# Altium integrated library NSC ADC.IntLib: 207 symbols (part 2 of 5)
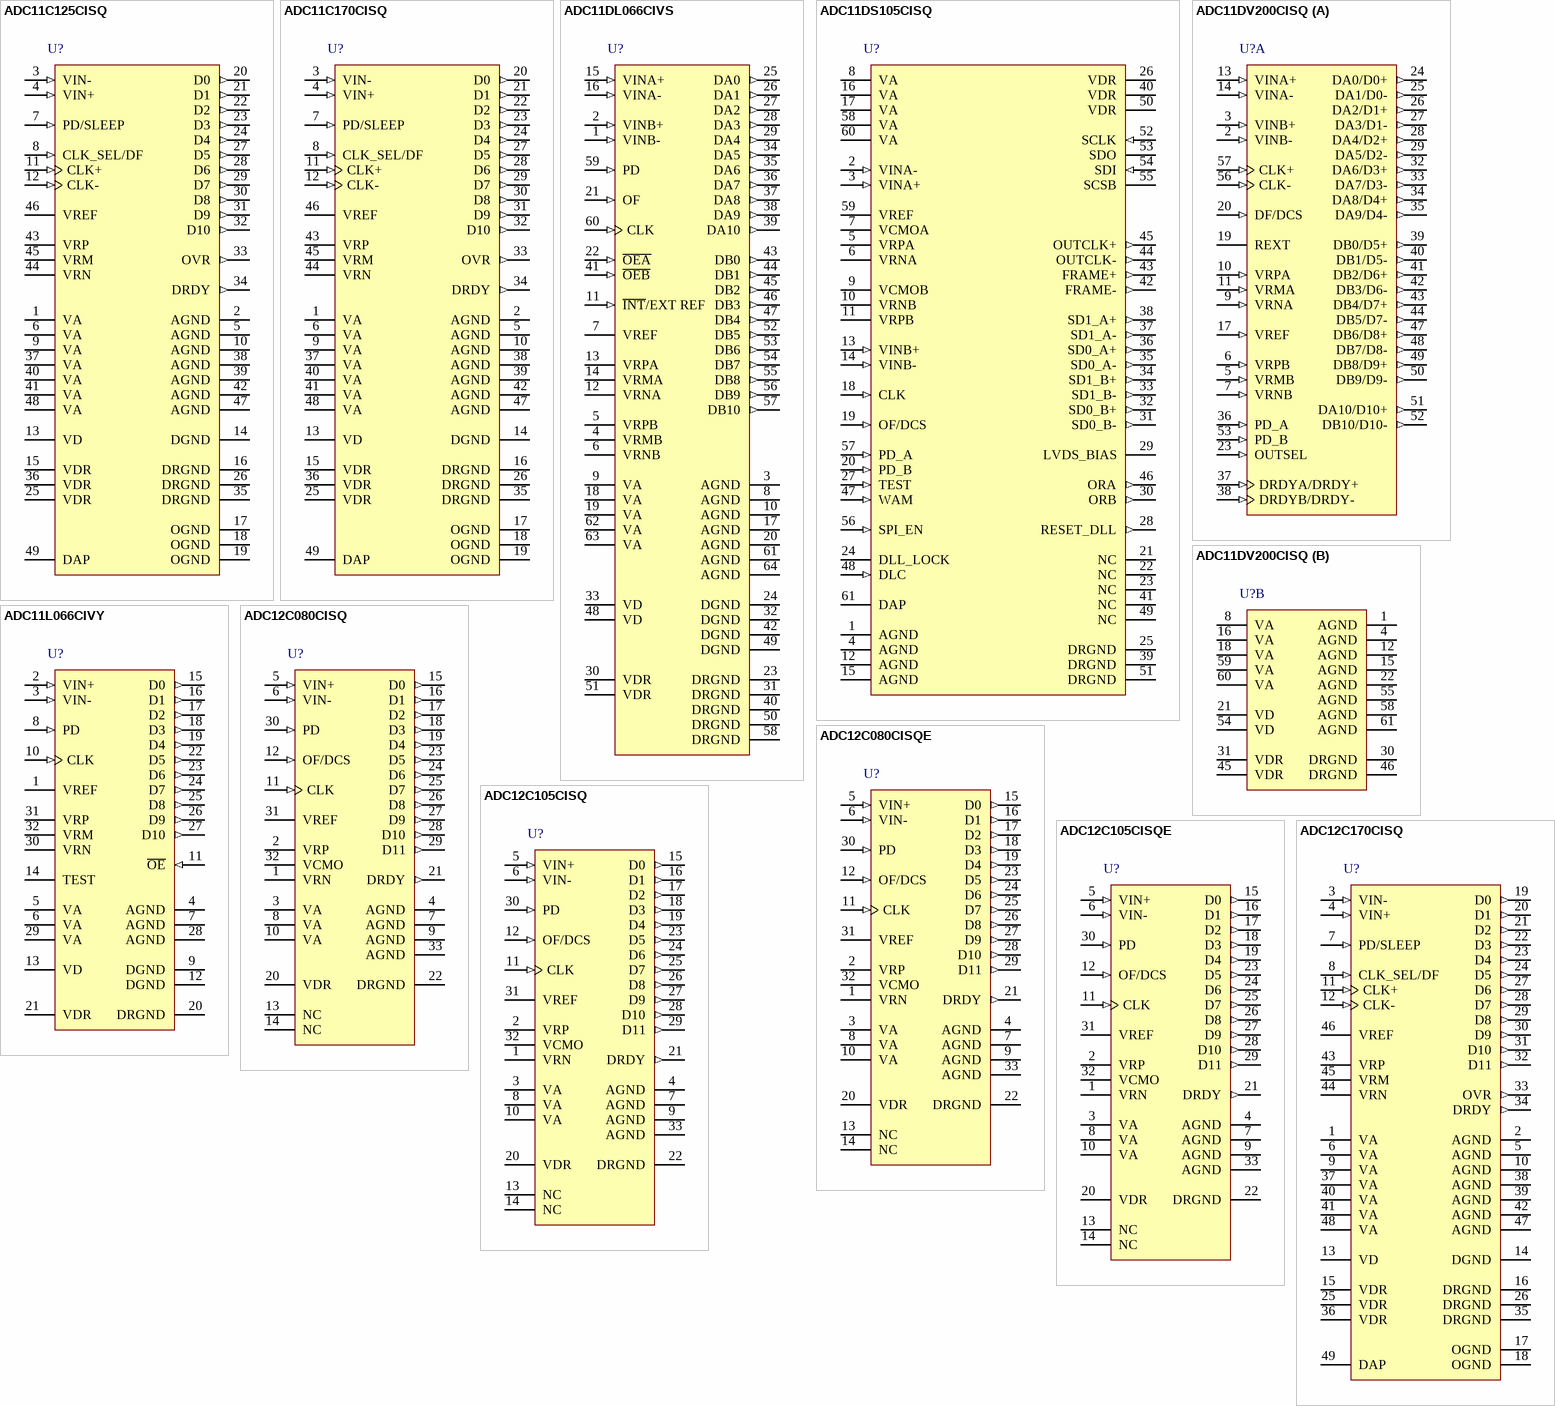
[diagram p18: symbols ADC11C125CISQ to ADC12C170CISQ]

## ADC11DS105CISQ
designator U?
Dual 11-Bit, 105 MSPS A/D Converter with Serial LVDS Outputs; PartNumber: ADC11DS105CISQ; Manufacturer: National Semiconductor; CompType: ADC IC; PackageTopMarking: NS*UZXYTT*11DS105; PowerWise: N
footprint SQA60A (QFN, 60-Leads, Body 9x9mm, Pitch 0.5mm, NSC Recommended)
pins: 1 AGND (power), 2 VINA- (in), 3 VINA+ (in), 4 AGND (power), 5 VRPA, 6 VRNA, 7 VCMOA, 8 VA (power), 9 VCMOB, 10 VRNB, 11 VRPB, 12 AGND (power), 13 VINB+ (in), 14 VINB- (in), 15 AGND (power), 16 VA (power), 17 VA (power), 18 CLK (in), 19 OF/DCS (in), 20 PD_B (in), 21 NC, 22 NC, 23 NC, 24 DLL_LOCK, 25 DRGND (power), 26 VDR, 27 TEST (in), 28 RESET_DLL (out), 29 LVDS_BIAS, 30 ORB (out), 31 SD0_B- (out), 32 SD0_B+ (out), 33 SD1_B- (out), 34 SD1_B+ (out), 35 SD0_A- (out), 36 SD0_A+ (out), 37 SD1_A- (out), 38 SD1_A+ (out), 39 DRGND (power), 40 VDR, 41 NC, 42 FRAME- (out), 43 FRAME+ (out), 44 OUTCLK- (out), 45 OUTCLK+ (out), 46 ORA (out), 47 WAM (in), 48 DLC (in), 49 NC, 50 VDR, 51 DRGND (power), 52 SCLK (in), 53 SDO (hiz), 54 SDI (in), 55 SCSB, 56 SPI_EN (in), 57 PD_A (in), 58 VA (power), 59 VREF, 60 VA (power), 61 DAP

## ADC11DV200CISQ
designator U?
Dual 11-bit, 200 MSPS Low-Power A/D Converter with Parallel LVDS/CMOS Outputs; PartNumber: ADC11DV200CISQ; Manufacturer: National Semiconductor; CompType: ADC IC; PackageTopMarking: NS*UZXYTT*11DV200*CISQ; PowerWise: N
footprint SQA60A (QFN, 60-Leads, Body 9x9mm, Pitch 0.5mm, NSC Recommended)
part A pins: 2 VINB- (in), 3 VINB+ (in), 5 VRMB (in), 6 VRPB (in), 7 VRNB (in), 9 VRNA (in), 10 VRPA (in), 11 VRMA (in), 13 VINA+ (in), 14 VINA- (in), 17 VREF (in), 19 REXT, 20 DF/DCS (in), 23 OUTSEL (in), 24 DA0/D0+ (out), 25 DA1/D0- (out), 26 DA2/D1+ (out), 27 DA3/D1- (out), 28 DA4/D2+ (out), 29 DA5/D2- (out), 32 DA6/D3+ (out), 33 DA7/D3- (out), 34 DA8/D4+ (out), 35 DA9/D4- (out), 36 PD_A (in), 37 DRDYA/DRDY+ (in), 38 DRDYB/DRDY- (in), 39 DB0/D5+ (out), 40 DB1/D5- (out), 41 DB2/D6+ (out), 42 DB3/D6- (out), 43 DB4/D7+ (out), 44 DB5/D7- (out), 47 DB6/D8+ (out), 48 DB7/D8- (out), 49 DB8/D9+ (out), 50 DB9/D9- (out), 51 DA10/D10+ (out), 52 DB10/D10- (out), 53 PD_B (in), 56 CLK- (in), 57 CLK+ (in)
part B pins: 1 AGND (power), 4 AGND (power), 8 VA (power), 12 AGND (power), 15 AGND (power), 16 VA (power), 18 VA (power), 21 VD (power), 22 AGND (power), 30 DRGND (power), 31 VDR (power), 45 VDR (power), 46 DRGND (power), 54 VD (power), 55 AGND (power), 58 AGND (power), 59 VA (power), 60 VA (power), 61 AGND (power)

## ADC11L066CIVY
designator U?
11-Bit, 66 MSPS, 450 MHz Bandwidth A/D Converter with Internal Sample-and-Hold; PartNumber: ADC11L066CIVY; Manufacturer: National Semiconductor; CompType: ADC IC; PackageTopMarking: NSUZXYTT*ADC11L0*66CIVY; PowerWise: N
footprint VBE32A_N (Thin QFP, 32-Leads, Body 7x7mm, Pitch 0.8mm, IPC Medium Density)
footprint VBE32A_L (Thin QFP, 32-Leads, Body 7x7mm, Pitch 0.8mm, IPC High Density)
footprint VBE32A_M (Thin QFP, 32-Leads, Body 7x7mm, Pitch 0.8mm, IPC Low Density)
pins: 1 VREF (power), 2 VIN+ (in), 3 VIN- (in), 4 AGND (power), 5 VA (power), 6 VA (power), 7 AGND (power), 8 PD (in), 9 DGND (power), 10 CLK (in), 11 ~{OE} (in), 12 DGND (power), 13 VD (power), 14 TEST, 15 D0 (out), 16 D1 (out), 17 D2 (out), 18 D3 (out), 19 D4 (out), 20 DRGND (power), 21 VDR (power), 22 D5 (out), 23 D6 (out), 24 D7 (out), 25 D8 (out), 26 D9 (out), 27 D10 (out), 28 AGND (power), 29 VA (power), 30 VRN, 31 VRP, 32 VRM

## ADC12C080CISQ
designator U?
12-Bit, 65/80 MSPS A/D Converter; PartNumber: ADC12C080CISQ; Manufacturer: National Semiconductor; CompType: ADC IC; PackageTopMarking: NS*UZXYTT*12C080; PowerWise: Y
footprint SQA32A (QFN, 32-Leads, Body 5x5mm, Pitch 0.5mm, NSC Recommended)
pins: 1 VRN, 2 VRP, 3 VA (power), 4 AGND (power), 5 VIN+ (in), 6 VIN- (in), 7 AGND (power), 8 VA (power), 9 AGND (power), 10 VA (power), 11 CLK (in), 12 OF/DCS (in), 13 NC, 14 NC, 15 D0 (out), 16 D1 (out), 17 D2 (out), 18 D3 (out), 19 D4 (out), 20 VDR (power), 21 DRDY (out), 22 DRGND (power), 23 D5 (out), 24 D6 (out), 25 D7 (out), 26 D8 (out), 27 D9 (out), 28 D10 (out), 29 D11 (out), 30 PD (in), 31 VREF (power), 32 VCMO, 33 AGND (power)

## ADC12C080CISQE
designator U?
12-Bit, 65/80 MSPS A/D Converter; PartNumber: ADC12C080CISQE; Manufacturer: National Semiconductor; CompType: ADC IC; PackageTopMarking: NS*UZXYTT*12C080E
footprint SQA32A (QFN, 32-Leads, Body 5x5mm, Pitch 0.5mm, NSC Recommended)
pins: 1 VRN, 2 VRP, 3 VA (power), 4 AGND (power), 5 VIN+ (in), 6 VIN- (in), 7 AGND (power), 8 VA (power), 9 AGND (power), 10 VA (power), 11 CLK (in), 12 OF/DCS (in), 13 NC, 14 NC, 15 D0 (out), 16 D1 (out), 17 D2 (out), 18 D3 (out), 19 D4 (out), 20 VDR (power), 21 DRDY (out), 22 DRGND (power), 23 D5 (out), 24 D6 (out), 25 D7 (out), 26 D8 (out), 27 D9 (out), 28 D10 (out), 29 D11 (out), 30 PD (in), 31 VREF (power), 32 VCMO, 33 AGND (power)

## ADC12C105CISQ
designator U?
12-Bit, 105 MSPS A/D Converter; PartNumber: ADC12C105CISQ; Manufacturer: National Semiconductor; CompType: ADC IC; PackageTopMarking: NS*UZXYTT*12C105; PowerWise: Y
footprint SQA32A (QFN, 32-Leads, Body 5x5mm, Pitch 0.5mm, NSC Recommended)
pins: 1 VRN, 2 VRP, 3 VA (power), 4 AGND (power), 5 VIN+ (in), 6 VIN- (in), 7 AGND (power), 8 VA (power), 9 AGND (power), 10 VA (power), 11 CLK (in), 12 OF/DCS (in), 13 NC, 14 NC, 15 D0 (out), 16 D1 (out), 17 D2 (out), 18 D3 (out), 19 D4 (out), 20 VDR (power), 21 DRDY (out), 22 DRGND (power), 23 D5 (out), 24 D6 (out), 25 D7 (out), 26 D8 (out), 27 D9 (out), 28 D10 (out), 29 D11 (out), 30 PD (in), 31 VREF (power), 32 VCMO, 33 AGND (power)

## ADC12C105CISQE
designator U?
12-Bit, 105 MSPS A/D Converter; PartNumber: ADC12C105CISQE; Manufacturer: National Semiconductor; CompType: ADC IC; PackageTopMarking: NS*UZXYTT*12C105E
footprint SQA32A (QFN, 32-Leads, Body 5x5mm, Pitch 0.5mm, NSC Recommended)
pins: 1 VRN, 2 VRP, 3 VA (power), 4 AGND (power), 5 VIN+ (in), 6 VIN- (in), 7 AGND (power), 8 VA (power), 9 AGND (power), 10 VA (power), 11 CLK (in), 12 OF/DCS (in), 13 NC, 14 NC, 15 D0 (out), 16 D1 (out), 17 D2 (out), 18 D3 (out), 19 D4 (out), 20 VDR (power), 21 DRDY (out), 22 DRGND (power), 23 D5 (out), 24 D6 (out), 25 D7 (out), 26 D8 (out), 27 D9 (out), 28 D10 (out), 29 D11 (out), 30 PD (in), 31 VREF (power), 32 VCMO, 33 AGND (power)

## ADC12C170CISQ
designator U?
12-Bit, 170 MSPS, 1.1 GHz Bandwidth A/D Converter with CMOS Outputs; PartNumber: ADC12C170CISQ; Manufacturer: National Semiconductor; CompType: ADC IC; PackageTopMarking: NS*UZXYTT*ADC12C170; PowerWise: Y
footprint SQA48A (QFN, 48-Leads, Body 7x7mm, Pitch 0.5mm, NSC Recommended)
pins: 1 VA (power), 2 AGND (power), 3 VIN- (in), 4 VIN+ (in), 5 AGND (power), 6 VA (power), 7 PD/SLEEP (in), 8 CLK_SEL/DF (in), 9 VA (power), 10 AGND (power), 11 CLK+ (in), 12 CLK- (in), 13 VD (power), 14 DGND (power), 15 VDR (power), 16 DRGND (power), 17 OGND (power), 18 OGND (power), 19 D0 (out), 20 D1 (out), 21 D2 (out), 22 D3 (out), 23 D4 (out), 24 D5 (out), 25 VDR (power), 26 DRGND (power), 27 D6 (out), 28 D7 (out), 29 D8 (out), 30 D9 (out), 31 D10 (out), 32 D11 (out), 33 OVR (out), 34 DRDY (out), 35 DRGND (power), 36 VDR (power), 37 VA (power), 38 AGND (power), 39 AGND (power), 40 VA (power), 41 VA (power), 42 AGND (power), 43 VRP, 44 VRN, 45 VRM, 46 VREF (power), 47 AGND (power), 48 VA (power), 49 DAP (power)

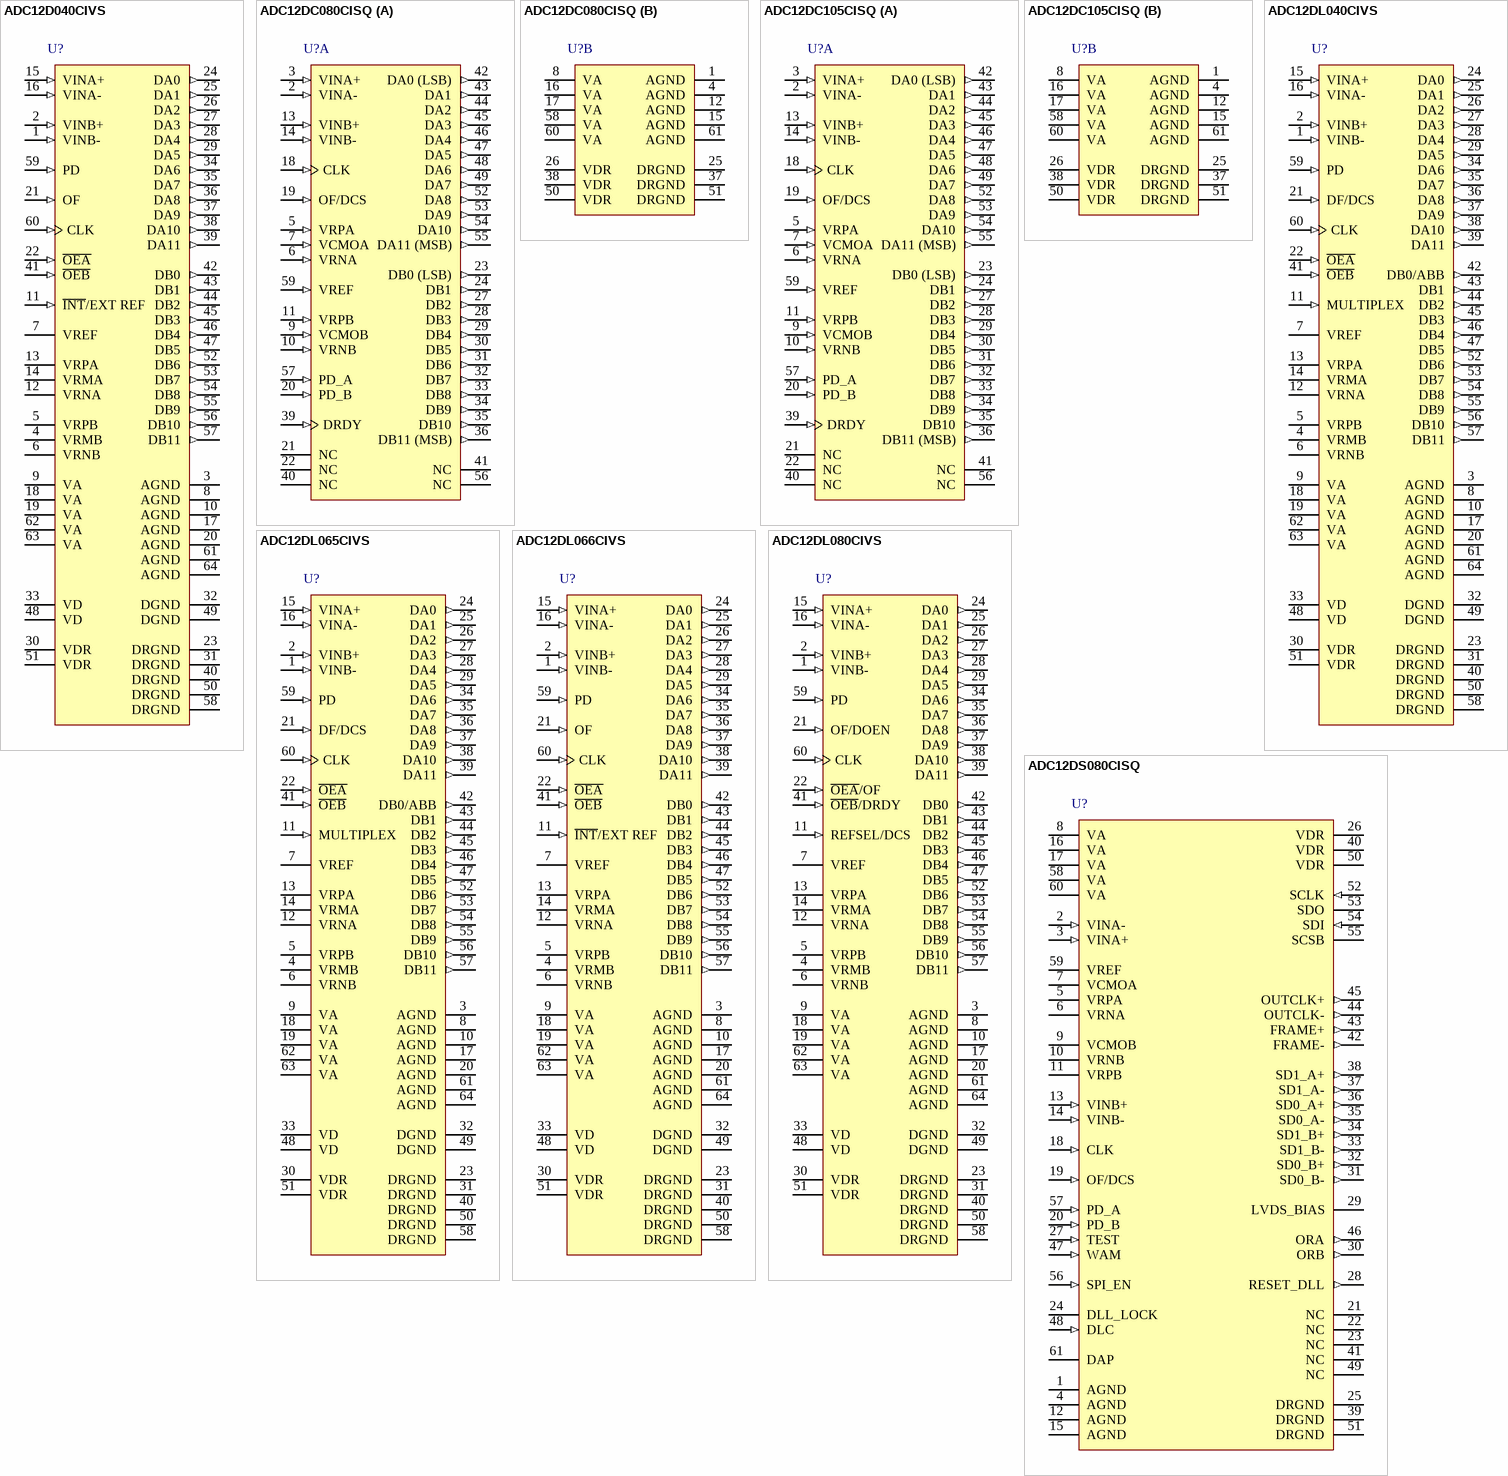
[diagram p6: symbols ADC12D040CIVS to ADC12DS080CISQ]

## ADC12D040CIVS
designator U?
Dual 12-Bit, 40 MSPS, 600 mW A/D Converter with Internal/External Reference; PartNumber: ADC12D040CIVS; Manufacturer: National Semiconductor; CompType: ADC IC; PackageTopMarking: NSUZXYYTT*ADC12D040*CIVS; PowerWise: N
footprint VEC64A_N (Thin QFP, 64-Leads, Body 10x10mm, Pitch 0.5mm, IPC Medium Density)
footprint VEC64A_L (Thin QFP, 64-Leads, Body 10x10mm, Pitch 0.5mm, IPC High Density)
footprint VEC64A_M (Thin QFP, 64-Leads, Body 10x10mm, Pitch 0.5mm, IPC Low Density)
pins: 1 VINB- (in), 2 VINB+ (in), 3 AGND (power), 4 VRMB, 5 VRPB, 6 VRNB, 7 VREF (power), 8 AGND (power), 9 VA (power), 10 AGND (power), 11 ~{INT}/EXT REF (in), 12 VRNA, 13 VRPA, 14 VRMA, 15 VINA+ (in), 16 VINA- (in), 17 AGND (power), 18 VA (power), 19 VA (power), 20 AGND (power), 21 OF (in), 22 ~{OEA} (in), 23 DRGND (power), 24 DA0 (out), 25 DA1 (out), 26 DA2 (out), 27 DA3 (out), 28 DA4 (out), 29 DA5 (out), 30 VDR (power), 31 DRGND (power), 32 DGND (power), 33 VD (power), 34 DA6 (out), 35 DA7 (out), 36 DA8 (out), 37 DA9 (out), 38 DA10 (out), 39 DA11 (out), 40 DRGND (power), 41 ~{OEB} (in), 42 DB0 (out), 43 DB1 (out), 44 DB2 (out), 45 DB3 (out), 46 DB4 (out), 47 DB5 (out), 48 VD (power), 49 DGND (power), 50 DRGND (power), 51 VDR (power), 52 DB6 (out), 53 DB7 (out), 54 DB8 (out), 55 DB9 (out), 56 DB10 (out), 57 DB11 (out), 58 DRGND (power), 59 PD (in), 60 CLK (in), 61 AGND (power), 62 VA (power), 63 VA (power), 64 AGND (power)

## ADC12DC080CISQ
designator U?
Dual 12-Bit, 80 MSPS A/D Converter with CMOS Outputs; PartNumber: ADC12DC080CISQ; Manufacturer: National Semiconductor; CompType: ADC IC; PackageTopMarking: NS*UZXYTT*12DC080*CISQ; PowerWise: Y
footprint SQA60A (QFN, 60-Leads, Body 9x9mm, Pitch 0.5mm, NSC Recommended)
part A pins: 2 VINA- (in), 3 VINA+ (in), 5 VRPA (in), 6 VRNA (in), 7 VCMOA (in), 9 VCMOB (in), 10 VRNB (in), 11 VRPB (in), 13 VINB+ (in), 14 VINB- (in), 18 CLK (in), 19 OF/DCS (in), 20 PD_B (in), 21 NC, 22 NC, 23 DB0 (LSB) (out), 24 DB1 (out), 27 DB2 (out), 28 DB3 (out), 29 DB4 (out), 30 DB5 (out), 31 DB6 (out), 32 DB7 (out), 33 DB8 (out), 34 DB9 (out), 35 DB10 (out), 36 DB11 (MSB) (out), 39 DRDY (in), 40 NC, 41 NC, 42 DA0 (LSB) (out), 43 DA1 (out), 44 DA2 (out), 45 DA3 (out), 46 DA4 (out), 47 DA5 (out), 48 DA6 (out), 49 DA7 (out), 52 DA8 (out), 53 DA9 (out), 54 DA10 (out), 55 DA11 (MSB) (out), 56 NC, 57 PD_A (in), 59 VREF (in)
part B pins: 1 AGND (power), 4 AGND (power), 8 VA (power), 12 AGND (power), 15 AGND (power), 16 VA (power), 17 VA (power), 25 DRGND (power), 26 VDR (power), 37 DRGND (power), 38 VDR (power), 50 VDR (power), 51 DRGND (power), 58 VA (power), 60 VA (power), 61 AGND (power)

## ADC12DC105CISQ
designator U?
Dual 12-Bit, 105 MSPS A/D Converter with CMOS Outputs; PartNumber: ADC12DC105CISQ; Manufacturer: National Semiconductor; CompType: ADC IC; PackageTopMarking: NS*UZXYTT*12DC105*CISQ; PowerWise: Y
footprint SQA60A (QFN, 60-Leads, Body 9x9mm, Pitch 0.5mm, NSC Recommended)
part A pins: 2 VINA- (in), 3 VINA+ (in), 5 VRPA (in), 6 VRNA (in), 7 VCMOA (in), 9 VCMOB (in), 10 VRNB (in), 11 VRPB (in), 13 VINB+ (in), 14 VINB- (in), 18 CLK (in), 19 OF/DCS (in), 20 PD_B (in), 21 NC, 22 NC, 23 DB0 (LSB) (out), 24 DB1 (out), 27 DB2 (out), 28 DB3 (out), 29 DB4 (out), 30 DB5 (out), 31 DB6 (out), 32 DB7 (out), 33 DB8 (out), 34 DB9 (out), 35 DB10 (out), 36 DB11 (MSB) (out), 39 DRDY (in), 40 NC, 41 NC, 42 DA0 (LSB) (out), 43 DA1 (out), 44 DA2 (out), 45 DA3 (out), 46 DA4 (out), 47 DA5 (out), 48 DA6 (out), 49 DA7 (out), 52 DA8 (out), 53 DA9 (out), 54 DA10 (out), 55 DA11 (MSB) (out), 56 NC, 57 PD_A (in), 59 VREF (in)
part B pins: 1 AGND (power), 4 AGND (power), 8 VA (power), 12 AGND (power), 15 AGND (power), 16 VA (power), 17 VA (power), 25 DRGND (power), 26 VDR (power), 37 DRGND (power), 38 VDR (power), 50 VDR (power), 51 DRGND (power), 58 VA (power), 60 VA (power), 61 AGND (power)

## ADC12DL040CIVS
designator U?
Dual 12-Bit, 40 MSPS, 3V, 210mW A/D Converter; PartNumber: ADC12DL040CIVS; Manufacturer: National Semiconductor; CompType: ADC IC; PackageTopMarking: NSUZXYYTT*ADC12DL040*CIVS; PowerWise: Y
footprint VEC64A_N (Thin QFP, 64-Leads, Body 10x10mm, Pitch 0.5mm, IPC Medium Density)
footprint VEC64A_L (Thin QFP, 64-Leads, Body 10x10mm, Pitch 0.5mm, IPC High Density)
footprint VEC64A_M (Thin QFP, 64-Leads, Body 10x10mm, Pitch 0.5mm, IPC Low Density)
pins: 1 VINB- (in), 2 VINB+ (in), 3 AGND (power), 4 VRMB, 5 VRPB, 6 VRNB, 7 VREF (power), 8 AGND (power), 9 VA (power), 10 AGND (power), 11 MULTIPLEX (in), 12 VRNA, 13 VRPA, 14 VRMA, 15 VINA+ (in), 16 VINA- (in), 17 AGND (power), 18 VA (power), 19 VA (power), 20 AGND (power), 21 DF/DCS (in), 22 ~{OEA} (in), 23 DRGND (power), 24 DA0 (out), 25 DA1 (out), 26 DA2 (out), 27 DA3 (out), 28 DA4 (out), 29 DA5 (out), 30 VDR (power), 31 DRGND (power), 32 DGND (power), 33 VD (power), 34 DA6 (out), 35 DA7 (out), 36 DA8 (out), 37 DA9 (out), 38 DA10 (out), 39 DA11 (out), 40 DRGND (power), 41 ~{OEB} (in), 42 DB0/ABB (out), 43 DB1 (out), 44 DB2 (out), 45 DB3 (out), 46 DB4 (out), 47 DB5 (out), 48 VD (power), 49 DGND (power), 50 DRGND (power), 51 VDR (power), 52 DB6 (out), 53 DB7 (out), 54 DB8 (out), 55 DB9 (out), 56 DB10 (out), 57 DB11 (out), 58 DRGND (power), 59 PD (in), 60 CLK (in), 61 AGND (power), 62 VA (power), 63 VA (power), 64 AGND (power)

## ADC12DL065CIVS
designator U?
Dual 12-Bit, 65 MSPS, A/D Converter; PartNumber: ADC12DL065CIVS; Manufacturer: National Semiconductor; CompType: ADC IC; PackageTopMarking: NSUZXYYTT*ADC12DL065*CIVS; PowerWise: Y
footprint VEC64A_N (Thin QFP, 64-Leads, Body 10x10mm, Pitch 0.5mm, IPC Medium Density)
footprint VEC64A_L (Thin QFP, 64-Leads, Body 10x10mm, Pitch 0.5mm, IPC High Density)
footprint VEC64A_M (Thin QFP, 64-Leads, Body 10x10mm, Pitch 0.5mm, IPC Low Density)
pins: 1 VINB- (in), 2 VINB+ (in), 3 AGND (power), 4 VRMB, 5 VRPB, 6 VRNB, 7 VREF (power), 8 AGND (power), 9 VA (power), 10 AGND (power), 11 MULTIPLEX (in), 12 VRNA, 13 VRPA, 14 VRMA, 15 VINA+ (in), 16 VINA- (in), 17 AGND (power), 18 VA (power), 19 VA (power), 20 AGND (power), 21 DF/DCS (in), 22 ~{OEA} (in), 23 DRGND (power), 24 DA0 (out), 25 DA1 (out), 26 DA2 (out), 27 DA3 (out), 28 DA4 (out), 29 DA5 (out), 30 VDR (power), 31 DRGND (power), 32 DGND (power), 33 VD (power), 34 DA6 (out), 35 DA7 (out), 36 DA8 (out), 37 DA9 (out), 38 DA10 (out), 39 DA11 (out), 40 DRGND (power), 41 ~{OEB} (in), 42 DB0/ABB (out), 43 DB1 (out), 44 DB2 (out), 45 DB3 (out), 46 DB4 (out), 47 DB5 (out), 48 VD (power), 49 DGND (power), 50 DRGND (power), 51 VDR (power), 52 DB6 (out), 53 DB7 (out), 54 DB8 (out), 55 DB9 (out), 56 DB10 (out), 57 DB11 (out), 58 DRGND (power), 59 PD (in), 60 CLK (in), 61 AGND (power), 62 VA (power), 63 VA (power), 64 AGND (power)

## ADC12DL066CIVS
designator U?
Dual 12-Bit, 66 MSPS, 450 MHz Input Bandwidth A/D Converter w/Internal Reference; PartNumber: ADC12DL066CIVS; Manufacturer: National Semiconductor; CompType: ADC IC; PackageTopMarking: NSUZXYYTT*ADC12DL066*CIVS; PowerWise: N
footprint VEC64A_N (Thin QFP, 64-Leads, Body 10x10mm, Pitch 0.5mm, IPC Medium Density)
footprint VEC64A_L (Thin QFP, 64-Leads, Body 10x10mm, Pitch 0.5mm, IPC High Density)
footprint VEC64A_M (Thin QFP, 64-Leads, Body 10x10mm, Pitch 0.5mm, IPC Low Density)
pins: 1 VINB- (in), 2 VINB+ (in), 3 AGND (power), 4 VRMB, 5 VRPB, 6 VRNB, 7 VREF (power), 8 AGND (power), 9 VA (power), 10 AGND (power), 11 ~{INT}/EXT REF (in), 12 VRNA, 13 VRPA, 14 VRMA, 15 VINA+ (in), 16 VINA- (in), 17 AGND (power), 18 VA (power), 19 VA (power), 20 AGND (power), 21 OF (in), 22 ~{OEA} (in), 23 DRGND (power), 24 DA0 (out), 25 DA1 (out), 26 DA2 (out), 27 DA3 (out), 28 DA4 (out), 29 DA5 (out), 30 VDR (power), 31 DRGND (power), 32 DGND (power), 33 VD (power), 34 DA6 (out), 35 DA7 (out), 36 DA8 (out), 37 DA9 (out), 38 DA10 (out), 39 DA11 (out), 40 DRGND (power), 41 ~{OEB} (in), 42 DB0 (out), 43 DB1 (out), 44 DB2 (out), 45 DB3 (out), 46 DB4 (out), 47 DB5 (out), 48 VD (power), 49 DGND (power), 50 DRGND (power), 51 VDR (power), 52 DB6 (out), 53 DB7 (out), 54 DB8 (out), 55 DB9 (out), 56 DB10 (out), 57 DB11 (out), 58 DRGND (power), 59 PD (in), 60 CLK (in), 61 AGND (power), 62 VA (power), 63 VA (power), 64 AGND (power)

## ADC12DL080CIVS
designator U?
Dual 12-Bit, 80 MSPS, A/D Converter; PartNumber: ADC12DL080CIVS; Manufacturer: National Semiconductor; CompType: ADC IC; PackageTopMarking: NSUZXYYTT*ADC12DL080*CIVS; PowerWise: Y
footprint VEC64A_N (Thin QFP, 64-Leads, Body 10x10mm, Pitch 0.5mm, IPC Medium Density)
footprint VEC64A_L (Thin QFP, 64-Leads, Body 10x10mm, Pitch 0.5mm, IPC High Density)
footprint VEC64A_M (Thin QFP, 64-Leads, Body 10x10mm, Pitch 0.5mm, IPC Low Density)
pins: 1 VINB- (in), 2 VINB+ (in), 3 AGND (power), 4 VRMB, 5 VRPB, 6 VRNB, 7 VREF (power), 8 AGND (power), 9 VA (power), 10 AGND (power), 11 REFSEL/DCS (in), 12 VRNA, 13 VRPA, 14 VRMA, 15 VINA+ (in), 16 VINA- (in), 17 AGND (power), 18 VA (power), 19 VA (power), 20 AGND (power), 21 OF/DOEN (in), 22 ~{OEA}/OF (in), 23 DRGND (power), 24 DA0 (out), 25 DA1 (out), 26 DA2 (out), 27 DA3 (out), 28 DA4 (out), 29 DA5 (out), 30 VDR (power), 31 DRGND (power), 32 DGND (power), 33 VD (power), 34 DA6 (out), 35 DA7 (out), 36 DA8 (out), 37 DA9 (out), 38 DA10 (out), 39 DA11 (out), 40 DRGND (power), 41 ~{OEB}/DRDY (in), 42 DB0 (out), 43 DB1 (out), 44 DB2 (out), 45 DB3 (out), 46 DB4 (out), 47 DB5 (out), 48 VD (power), 49 DGND (power), 50 DRGND (power), 51 VDR (power), 52 DB6 (out), 53 DB7 (out), 54 DB8 (out), 55 DB9 (out), 56 DB10 (out), 57 DB11 (out), 58 DRGND (power), 59 PD (in), 60 CLK (in), 61 AGND (power), 62 VA (power), 63 VA (power), 64 AGND (power)

## ADC12DS080CISQ
designator U?
Dual 12-Bit, 80 MSPS A/D Converter with Serial LVDS Outputs; PartNumber: ADC12DS080CISQ; Manufacturer: National Semiconductor; CompType: ADC IC; PackageTopMarking: NS*UZXYTT*12DS080; PowerWise: Y
footprint SQA60A (QFN, 60-Leads, Body 9x9mm, Pitch 0.5mm, NSC Recommended)
pins: 1 AGND (power), 2 VINA- (in), 3 VINA+ (in), 4 AGND (power), 5 VRPA, 6 VRNA, 7 VCMOA, 8 VA (power), 9 VCMOB, 10 VRNB, 11 VRPB, 12 AGND (power), 13 VINB+ (in), 14 VINB- (in), 15 AGND (power), 16 VA (power), 17 VA (power), 18 CLK (in), 19 OF/DCS (in), 20 PD_B (in), 21 NC, 22 NC, 23 NC, 24 DLL_LOCK, 25 DRGND (power), 26 VDR, 27 TEST (in), 28 RESET_DLL (out), 29 LVDS_BIAS, 30 ORB (out), 31 SD0_B- (out), 32 SD0_B+ (out), 33 SD1_B- (out), 34 SD1_B+ (out), 35 SD0_A- (out), 36 SD0_A+ (out), 37 SD1_A- (out), 38 SD1_A+ (out), 39 DRGND (power), 40 VDR, 41 NC, 42 FRAME- (out), 43 FRAME+ (out), 44 OUTCLK- (out), 45 OUTCLK+ (out), 46 ORA (out), 47 WAM (in), 48 DLC (in), 49 NC, 50 VDR, 51 DRGND (power), 52 SCLK (in), 53 SDO (hiz), 54 SDI (in), 55 SCSB, 56 SPI_EN (in), 57 PD_A (in), 58 VA (power), 59 VREF, 60 VA (power), 61 DAP

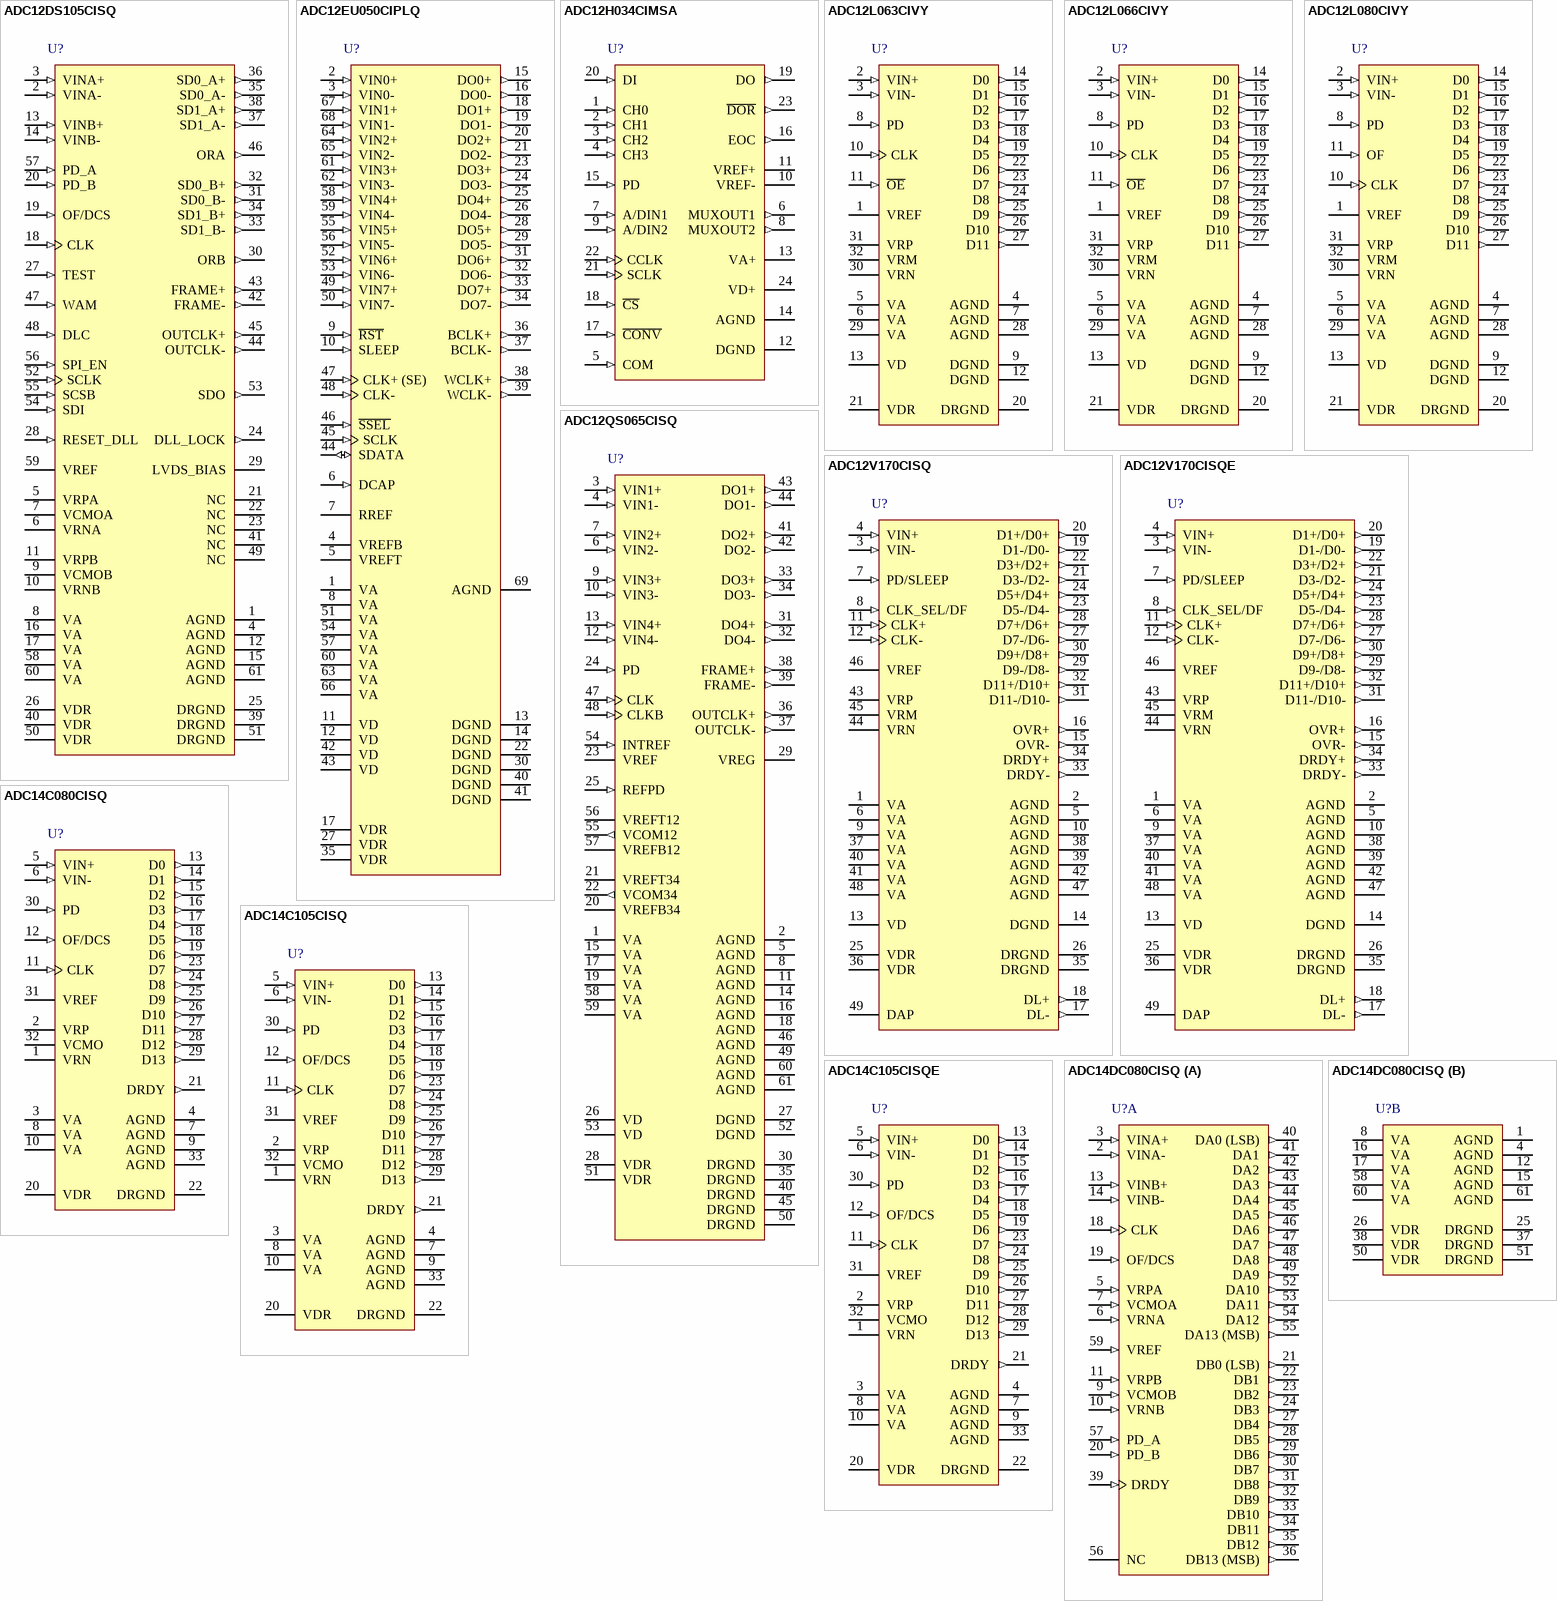
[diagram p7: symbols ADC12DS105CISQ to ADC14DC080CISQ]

## ADC12DS105CISQ
designator U?
Dual 12-Bit, 105 MSPS A/D Converter with Serial LVDS Outputs; PartNumber: ADC12DS105CISQ; Manufacturer: National Semiconductor; CompType: ADC IC; PackageTopMarking: NS*UZXYTT*12DS105; PowerWise: Y
footprint SQA60A (QFN, 60-Leads, Body 9x9mm, Pitch 0.5mm, NSC Recommended)
pins: 1 AGND (power), 2 VINA- (in), 3 VINA+ (in), 4 AGND (power), 5 VRPA, 6 VRNA, 7 VCMOA, 8 VA (power), 9 VCMOB, 10 VRNB, 11 VRPB, 12 AGND (power), 13 VINB+ (in), 14 VINB- (in), 15 AGND (power), 16 VA (power), 17 VA (power), 18 CLK (in), 19 OF/DCS (in), 20 PD_B (in), 21 NC, 22 NC, 23 NC, 24 DLL_LOCK (out), 25 DRGND (power), 26 VDR (power), 27 TEST (in), 28 RESET_DLL (in), 29 LVDS_BIAS, 30 ORB (out), 31 SD0_B- (out), 32 SD0_B+ (out), 33 SD1_B- (out), 34 SD1_B+ (out), 35 SD0_A- (out), 36 SD0_A+ (out), 37 SD1_A- (out), 38 SD1_A+ (out), 39 DRGND (power), 40 VDR (power), 41 NC, 42 FRAME- (out), 43 FRAME+ (out), 44 OUTCLK- (out), 45 OUTCLK+ (out), 46 ORA (out), 47 WAM (in), 48 DLC (in), 49 NC, 50 VDR (power), 51 DRGND (power), 52 SCLK (in), 53 SDO (out), 54 SDI (in), 55 SCSB (in), 56 SPI_EN (in), 57 PD_A (in), 58 VA (power), 59 VREF (power), 60 VA (power), 61 AGND (power)

## ADC12EU050CIPLQ
designator U?
Ultra-Low Power, Octal, 12-bit, 40-50 MSPS Sigma-Delta Analog-to-Digital Converter; PartNumber: ADC12EU050CIPLQ; Manufacturer: National Semiconductor; CompType: ADC IC; PackageTopMarking: NS*UZXYTT*12EU050P; PowerWise: N
footprint LQA68A (QFN, 68-Leads, Body 10x10mm, Pitch 0.5mm, NSC Recommended)
pins: 1 VA (power), 2 VIN0+ (in), 3 VIN0- (in), 4 VREFB (power), 5 VREFT (power), 6 DCAP (in), 7 RREF, 8 VA (power), 9 ~{RST} (in), 10 SLEEP (in), 11 VD (power), 12 VD (power), 13 DGND (power), 14 DGND (power), 15 DO0+ (out), 16 DO0- (out), 17 VDR (power), 18 DO1+ (out), 19 DO1- (out), 20 DO2+ (out), 21 DO2- (out), 22 DGND (power), 23 DO3+ (out), 24 DO3- (out), 25 DO4+ (out), 26 DO4- (out), 27 VDR (power), 28 DO5+ (out), 29 DO5- (out), 30 DGND (power), 31 DO6+ (out), 32 DO6- (out), 33 DO7+ (out), 34 DO7- (out), 35 VDR (power), 36 BCLK+ (out), 37 BCLK- (out), 38 WCLK+ (out), 39 WCLK- (out), 40 DGND (power), 41 DGND (power), 42 VD (power), 43 VD (power), 44 SDATA (io), 45 SCLK (in), 46 ~{SSEL} (in), 47 CLK+ (SE) (in), 48 CLK- (in), 49 VIN7+ (in), 50 VIN7- (in), 51 VA (power), 52 VIN6+ (in), 53 VIN6- (in), 54 VA (power), 55 VIN5+ (in), 56 VIN5- (in), 57 VA (power), 58 VIN4+ (in), 59 VIN4- (in), 60 VA (power), 61 VIN3+ (in), 62 VIN3- (in), 63 VA (power), 64 VIN2+ (in), 65 VIN2- (in), 66 VA (power), 67 VIN1+ (in), 68 VIN1- (in), 69 AGND (power)

## ADC12H034CIMSA
designator U?
Self-Calibrating 12-Bit Plus Sign Serial I/O A/D Converters with MUX and Sample/Hold; PartNumber: ADC12H034CIMSA; Manufacturer: National Semiconductor; CompType: ADC IC; PackageTopMarking: NSUZXYTT*ADC12H034*CIMSA; PowerWise: N
footprint MSA24_N (SOP, 24-Leads, Body 8.2x5.3mm, Pitch 0.65mm, IPC Medium Density)
footprint MSA24_L (SOP, 24-Leads, Body 8.2x5.3mm, Pitch 0.65mm, IPC High Density)
footprint MSA24_M (SOP, 24-Leads, Body 8.2x5.3mm, Pitch 0.65mm, IPC Low Density)
pins: 1 CH0 (in), 2 CH1 (in), 3 CH2 (in), 4 CH3 (in), 5 COM (in), 6 MUXOUT1 (out), 7 A/DIN1 (in), 8 MUXOUT2 (out), 9 A/DIN2 (in), 10 VREF- (power), 11 VREF+ (power), 12 DGND (power), 13 VA+ (power), 14 AGND (power), 15 PD (in), 16 EOC (out), 17 ~{CONV} (in), 18 ~{CS} (in), 19 DO (out), 20 DI (in), 21 SCLK (in), 22 CCLK (in), 23 ~{DOR} (out), 24 VD+ (power)

## ADC12L063CIVY
designator U?
12-Bit, 62 MSPS, 354mW A/D Converter with Internal Sample-and-Hold; PartNumber: ADC12L063CIVY; Manufacturer: National Semiconductor; CompType: ADC IC; PackageTopMarking: NSUZXYTT*ADC12L0*63CIVY; PowerWise: N
footprint VBE32A_N (Thin QFP, 32-Leads, Body 7x7mm, Pitch 0.8mm, IPC Medium Density)
footprint VBE32A_L (Thin QFP, 32-Leads, Body 7x7mm, Pitch 0.8mm, IPC High Density)
footprint VBE32A_M (Thin QFP, 32-Leads, Body 7x7mm, Pitch 0.8mm, IPC Low Density)
pins: 1 VREF (power), 2 VIN+ (in), 3 VIN- (in), 4 AGND (power), 5 VA (power), 6 VA (power), 7 AGND (power), 8 PD (in), 9 DGND (power), 10 CLK (in), 11 ~{OE} (in), 12 DGND (power), 13 VD (power), 14 D0 (out), 15 D1 (out), 16 D2 (out), 17 D3 (out), 18 D4 (out), 19 D5 (out), 20 DRGND (power), 21 VDR (power), 22 D6 (out), 23 D7 (out), 24 D8 (out), 25 D9 (out), 26 D10 (out), 27 D11 (out), 28 AGND (power), 29 VA (power), 30 VRN, 31 VRP, 32 VRM

## ADC12L066CIVY
designator U?
12-Bit, 66 MSPS, 450 MHz Bandwidth A/D Converter with Internal Sample-and-Hold; PartNumber: ADC12L066CIVY; Manufacturer: National Semiconductor; CompType: ADC IC; PackageTopMarking: NSUZXYTT*ADC12L0*66CIVY; PowerWise: N
footprint VBE32A_N (Thin QFP, 32-Leads, Body 7x7mm, Pitch 0.8mm, IPC Medium Density)
footprint VBE32A_L (Thin QFP, 32-Leads, Body 7x7mm, Pitch 0.8mm, IPC High Density)
footprint VBE32A_M (Thin QFP, 32-Leads, Body 7x7mm, Pitch 0.8mm, IPC Low Density)
pins: 1 VREF (power), 2 VIN+ (in), 3 VIN- (in), 4 AGND (power), 5 VA (power), 6 VA (power), 7 AGND (power), 8 PD (in), 9 DGND (power), 10 CLK (in), 11 ~{OE} (in), 12 DGND (power), 13 VD (power), 14 D0 (out), 15 D1 (out), 16 D2 (out), 17 D3 (out), 18 D4 (out), 19 D5 (out), 20 DRGND (power), 21 VDR (power), 22 D6 (out), 23 D7 (out), 24 D8 (out), 25 D9 (out), 26 D10 (out), 27 D11 (out), 28 AGND (power), 29 VA (power), 30 VRN, 31 VRP, 32 VRM

## ADC12L080CIVY
designator U?
12-Bit, 80 MSPS, 450 MHz Bandwidth A/D Converter with Internal Reference; PartNumber: ADC12L080CIVY; Manufacturer: National Semiconductor; CompType: ADC IC; PackageTopMarking: NSUZXYTT*ADC12L0*80CIVY; PowerWise: N
footprint VBE32A_N (Thin QFP, 32-Leads, Body 7x7mm, Pitch 0.8mm, IPC Medium Density)
footprint VBE32A_L (Thin QFP, 32-Leads, Body 7x7mm, Pitch 0.8mm, IPC High Density)
footprint VBE32A_M (Thin QFP, 32-Leads, Body 7x7mm, Pitch 0.8mm, IPC Low Density)
pins: 1 VREF (power), 2 VIN+ (in), 3 VIN- (in), 4 AGND (power), 5 VA (power), 6 VA (power), 7 AGND (power), 8 PD (in), 9 DGND (power), 10 CLK (in), 11 OF (in), 12 DGND (power), 13 VD (power), 14 D0 (out), 15 D1 (out), 16 D2 (out), 17 D3 (out), 18 D4 (out), 19 D5 (out), 20 DRGND (power), 21 VDR (power), 22 D6 (out), 23 D7 (out), 24 D8 (out), 25 D9 (out), 26 D10 (out), 27 D11 (out), 28 AGND (power), 29 VA (power), 30 VRN, 31 VRP, 32 VRM

## ADC12QS065CISQ
designator U?
Quad 12-Bit 65 MSPS A/D Converter with LVDS Serialized Outputs; PartNumber: ADC12QS065CISQ; Manufacturer: National Semiconductor; CompType: ADC IC; PackageTopMarking: NS*UZXYTT*12QS065*CISQ; PowerWise: Y
footprint SQA60A (QFN, 60-Leads, Body 9x9mm, Pitch 0.5mm, NSC Recommended)
pins: 1 VA (power), 2 AGND (power), 3 VIN1+ (in), 4 VIN1- (in), 5 AGND (power), 6 VIN2- (in), 7 VIN2+ (in), 8 AGND (power), 9 VIN3+ (in), 10 VIN3- (in), 11 AGND (power), 12 VIN4- (in), 13 VIN4+ (in), 14 AGND (power), 15 VA (power), 16 AGND (power), 17 VA (power), 18 AGND (power), 19 VA (power), 20 VREFB34 (power), 21 VREFT34 (power), 22 VCOM34 (out), 23 VREF (power), 24 PD (in), 25 REFPD (in), 26 VD (power), 27 DGND (power), 28 VDR (power), 29 VREG, 30 DRGND (power), 31 DO4+ (out), 32 DO4- (out), 33 DO3+ (out), 34 DO3- (out), 35 DRGND (power), 36 OUTCLK+ (out), 37 OUTCLK- (out), 38 FRAME+ (out), 39 FRAME- (out), 40 DRGND (power), 41 DO2+ (out), 42 DO2- (out), 43 DO1+ (out), 44 DO1- (out), 45 DRGND (power), 46 AGND (power), 47 CLK (in), 48 CLKB (in), 49 AGND (power), 50 DRGND (power), 51 VDR (power), 52 DGND (power), 53 VD (power), 54 INTREF (in), 55 VCOM12 (out), 56 VREFT12 (power), 57 VREFB12 (power), 58 VA (power), 59 VA (power), 60 AGND (power), 61 AGND (power)

## ADC12V170CISQ
designator U?
12-Bit, 170 MSPS, 1.1 GHz Bandwidth A/D Converter with LVDS Outputs; PartNumber: ADC12V170CISQ; Manufacturer: National Semiconductor; CompType: ADC IC; PackageTopMarking: NS*UZXYTT*ADC12V170; PowerWise: Y
footprint SQA48A (QFN, 48-Leads, Body 7x7mm, Pitch 0.5mm, NSC Recommended)
pins: 1 VA (power), 2 AGND (power), 3 VIN- (in), 4 VIN+ (in), 5 AGND (power), 6 VA (power), 7 PD/SLEEP (in), 8 CLK_SEL/DF (in), 9 VA (power), 10 AGND (power), 11 CLK+ (in), 12 CLK- (in), 13 VD (power), 14 DGND (power), 15 OVR- (out), 16 OVR+ (out), 17 DL- (out), 18 DL+ (out), 19 D1-/D0- (out), 20 D1+/D0+ (out), 21 D3-/D2- (out), 22 D3+/D2+ (out), 23 D5-/D4- (out), 24 D5+/D4+ (out), 25 VDR (power), 26 DRGND (power), 27 D7-/D6- (out), 28 D7+/D6+ (out), 29 D9-/D8- (out), 30 D9+/D8+ (out), 31 D11-/D10- (out), 32 D11+/D10+ (out), 33 DRDY- (out), 34 DRDY+ (out), 35 DRGND (power), 36 VDR (power), 37 VA (power), 38 AGND (power), 39 AGND (power), 40 VA (power), 41 VA (power), 42 AGND (power), 43 VRP, 44 VRN, 45 VRM, 46 VREF (power), 47 AGND (power), 48 VA (power), 49 DAP (power)

## ADC12V170CISQE
designator U?
12-Bit, 170 MSPS, 1.1 GHz Bandwidth A/D Converter with LVDS Outputs; PartNumber: ADC12V170CISQE; Manufacturer: National Semiconductor; CompType: ADC IC; PackageTopMarking: NS*UZXYTT*12V170SQE
footprint SQA48A (QFN, 48-Leads, Body 7x7mm, Pitch 0.5mm, NSC Recommended)
pins: 1 VA (power), 2 AGND (power), 3 VIN- (in), 4 VIN+ (in), 5 AGND (power), 6 VA (power), 7 PD/SLEEP (in), 8 CLK_SEL/DF (in), 9 VA (power), 10 AGND (power), 11 CLK+ (in), 12 CLK- (in), 13 VD (power), 14 DGND (power), 15 OVR- (out), 16 OVR+ (out), 17 DL- (out), 18 DL+ (out), 19 D1-/D0- (out), 20 D1+/D0+ (out), 21 D3-/D2- (out), 22 D3+/D2+ (out), 23 D5-/D4- (out), 24 D5+/D4+ (out), 25 VDR (power), 26 DRGND (power), 27 D7-/D6- (out), 28 D7+/D6+ (out), 29 D9-/D8- (out), 30 D9+/D8+ (out), 31 D11-/D10- (out), 32 D11+/D10+ (out), 33 DRDY- (out), 34 DRDY+ (out), 35 DRGND (power), 36 VDR (power), 37 VA (power), 38 AGND (power), 39 AGND (power), 40 VA (power), 41 VA (power), 42 AGND (power), 43 VRP, 44 VRN, 45 VRM, 46 VREF (power), 47 AGND (power), 48 VA (power), 49 DAP (power)

## ADC14C080CISQ
designator U?
14-Bit, 65/80 MSPS A/D Converter; PartNumber: ADC14C080CISQ; Manufacturer: National Semiconductor; CompType: ADC IC; PackageTopMarking: NS*UZXYTT*14C080; PowerWise: Y
footprint SQA32A (QFN, 32-Leads, Body 5x5mm, Pitch 0.5mm, NSC Recommended)
pins: 1 VRN, 2 VRP, 3 VA (power), 4 AGND (power), 5 VIN+ (in), 6 VIN- (in), 7 AGND (power), 8 VA (power), 9 AGND (power), 10 VA (power), 11 CLK (in), 12 OF/DCS (in), 13 D0 (out), 14 D1 (out), 15 D2 (out), 16 D3 (out), 17 D4 (out), 18 D5 (out), 19 D6 (out), 20 VDR (power), 21 DRDY (out), 22 DRGND (power), 23 D7 (out), 24 D8 (out), 25 D9 (out), 26 D10 (out), 27 D11 (out), 28 D12 (out), 29 D13 (out), 30 PD (in), 31 VREF (power), 32 VCMO, 33 AGND (power)

## ADC14C105CISQ
designator U?
14-Bit, 105 MSPS A/D Converter; PartNumber: ADC14C105CISQ; Manufacturer: National Semiconductor; CompType: ADC IC; PackageTopMarking: NS*UZXYTT*14C105; PowerWise: Y
footprint SQA32A (QFN, 32-Leads, Body 5x5mm, Pitch 0.5mm, NSC Recommended)
pins: 1 VRN, 2 VRP, 3 VA (power), 4 AGND (power), 5 VIN+ (in), 6 VIN- (in), 7 AGND (power), 8 VA (power), 9 AGND (power), 10 VA (power), 11 CLK (in), 12 OF/DCS (in), 13 D0 (out), 14 D1 (out), 15 D2 (out), 16 D3 (out), 17 D4 (out), 18 D5 (out), 19 D6 (out), 20 VDR (power), 21 DRDY (out), 22 DRGND (power), 23 D7 (out), 24 D8 (out), 25 D9 (out), 26 D10 (out), 27 D11 (out), 28 D12 (out), 29 D13 (out), 30 PD (in), 31 VREF (power), 32 VCMO, 33 AGND (power)

## ADC14C105CISQE
designator U?
14-Bit, 105 MSPS A/D Converter; PartNumber: ADC14C105CISQE; Manufacturer: National Semiconductor; CompType: ADC IC; PackageTopMarking: NS*UZXYTT*14C105E
footprint SQA32A (QFN, 32-Leads, Body 5x5mm, Pitch 0.5mm, NSC Recommended)
pins: 1 VRN, 2 VRP, 3 VA (power), 4 AGND (power), 5 VIN+ (in), 6 VIN- (in), 7 AGND (power), 8 VA (power), 9 AGND (power), 10 VA (power), 11 CLK (in), 12 OF/DCS (in), 13 D0 (out), 14 D1 (out), 15 D2 (out), 16 D3 (out), 17 D4 (out), 18 D5 (out), 19 D6 (out), 20 VDR (power), 21 DRDY (out), 22 DRGND (power), 23 D7 (out), 24 D8 (out), 25 D9 (out), 26 D10 (out), 27 D11 (out), 28 D12 (out), 29 D13 (out), 30 PD (in), 31 VREF (power), 32 VCMO, 33 AGND (power)

## ADC14DC080CISQ
designator U?
Dual 14-Bit, 80 MSPS A/D Converter with CMOS Outputs; PartNumber: ADC14DC080CISQ; Manufacturer: National Semiconductor; CompType: ADC IC; PackageTopMarking: NS*UZXYTT*14DC080*CISQ; PowerWise: Y
footprint SQA60A (QFN, 60-Leads, Body 9x9mm, Pitch 0.5mm, NSC Recommended)
part A pins: 2 VINA- (in), 3 VINA+ (in), 5 VRPA (in), 6 VRNA (in), 7 VCMOA (in), 9 VCMOB (in), 10 VRNB (in), 11 VRPB (in), 13 VINB+ (in), 14 VINB- (in), 18 CLK (in), 19 OF/DCS (in), 20 PD_B (in), 21 DB0 (LSB) (out), 22 DB1 (out), 23 DB2 (out), 24 DB3 (out), 27 DB4 (out), 28 DB5 (out), 29 DB6 (out), 30 DB7 (out), 31 DB8 (out), 32 DB9 (out), 33 DB10 (out), 34 DB11 (out), 35 DB12 (out), 36 DB13 (MSB) (out), 39 DRDY (in), 40 DA0 (LSB) (out), 41 DA1 (out), 42 DA2 (out), 43 DA3 (out), 44 DA4 (out), 45 DA5 (out), 46 DA6 (out), 47 DA7 (out), 48 DA8 (out), 49 DA9 (out), 52 DA10 (out), 53 DA11 (out), 54 DA12 (out), 55 DA13 (MSB) (out), 56 NC, 57 PD_A (in), 59 VREF (in)
part B pins: 1 AGND (power), 4 AGND (power), 8 VA (power), 12 AGND (power), 15 AGND (power), 16 VA (power), 17 VA (power), 25 DRGND (power), 26 VDR (power), 37 DRGND (power), 38 VDR (power), 50 VDR (power), 51 DRGND (power), 58 VA (power), 60 VA (power), 61 AGND (power)

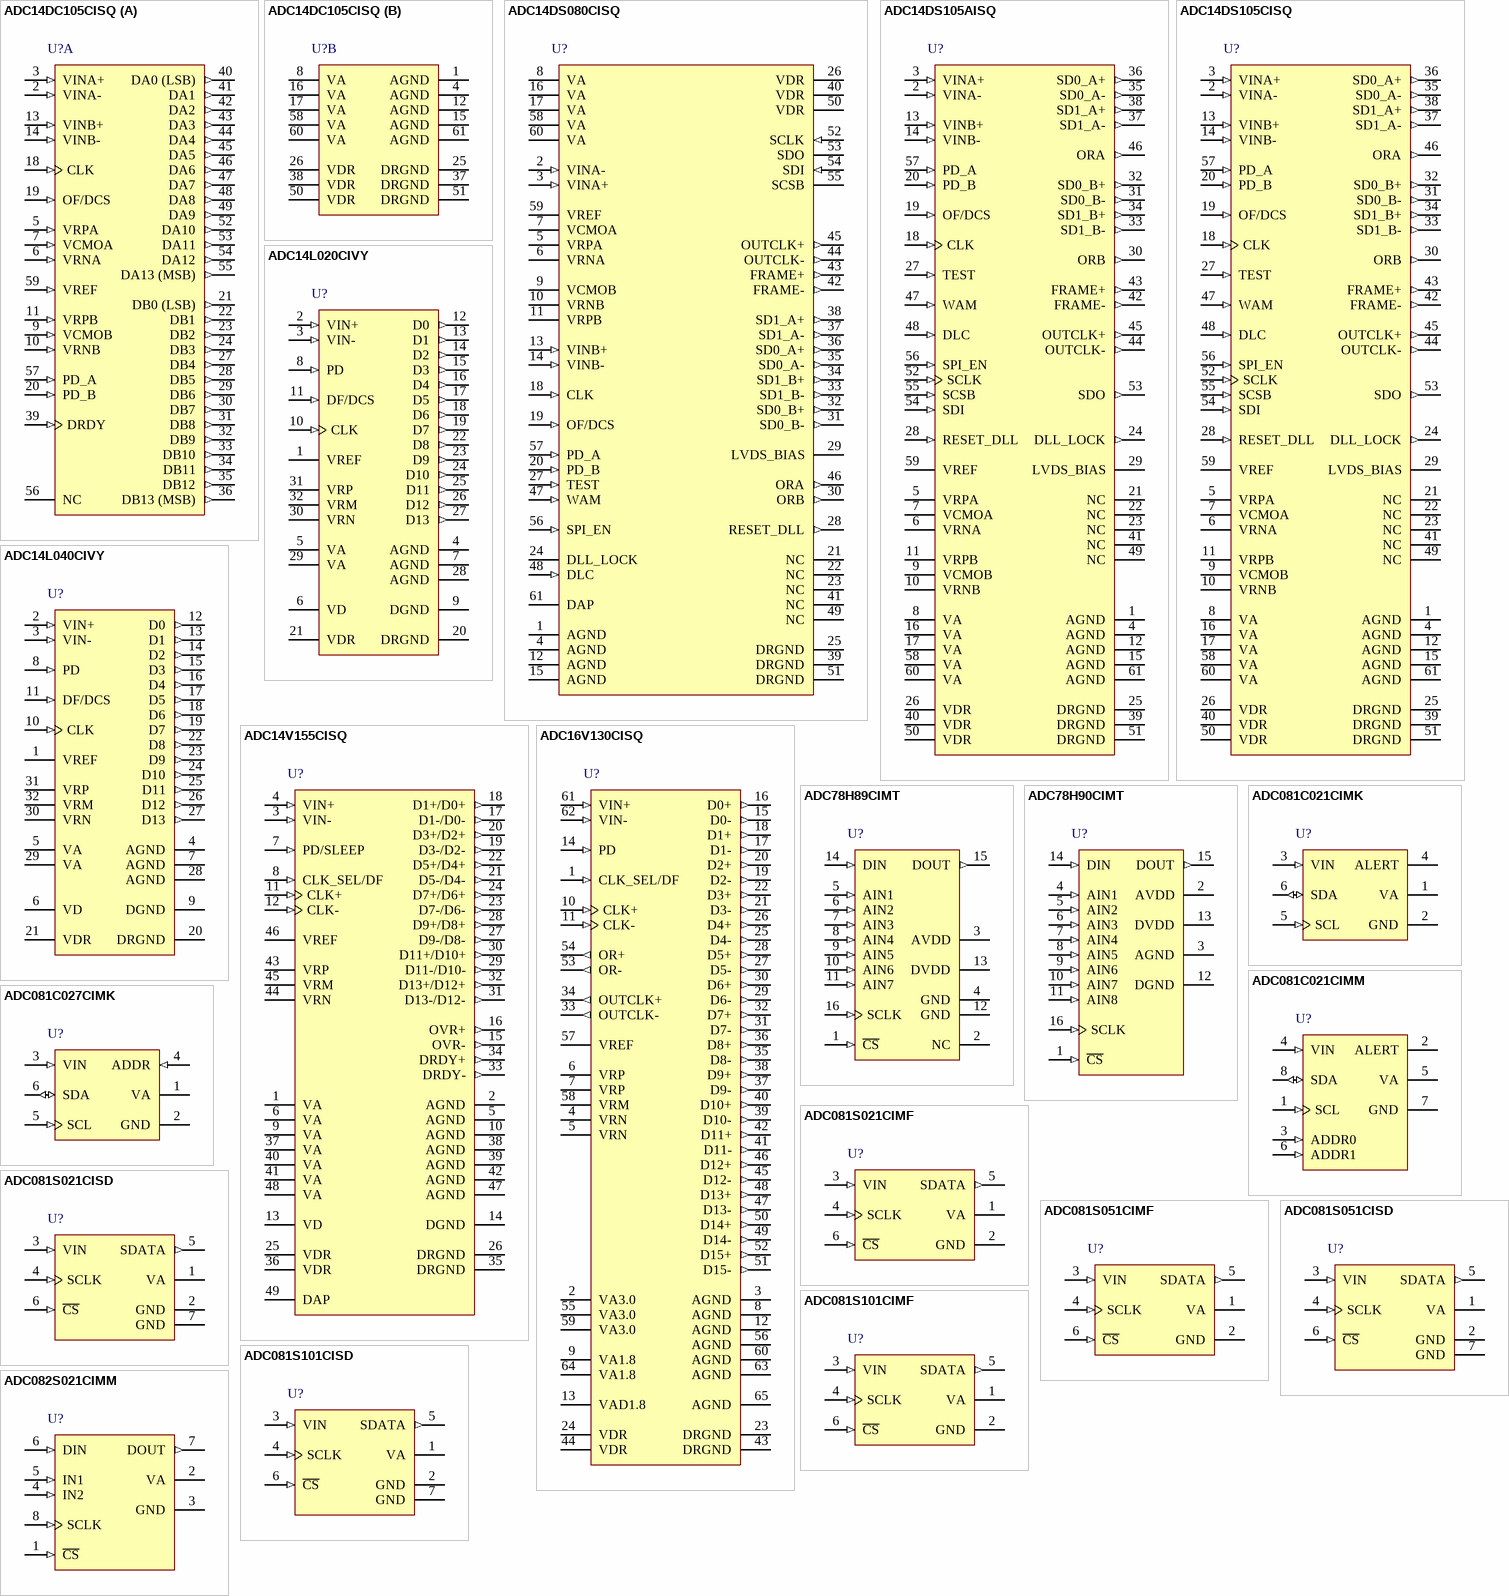
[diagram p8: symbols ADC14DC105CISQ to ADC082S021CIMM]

## ADC14DC105CISQ
designator U?
Dual 14-Bit, 105 MSPS A/D Converter with CMOS Outputs; PartNumber: ADC14DC105CISQ; Manufacturer: National Semiconductor; CompType: ADC IC; PackageTopMarking: NS*UZXYTT*14DC105*CISQ; PowerWise: Y
footprint SQA60A (QFN, 60-Leads, Body 9x9mm, Pitch 0.5mm, NSC Recommended)
part A pins: 2 VINA- (in), 3 VINA+ (in), 5 VRPA (in), 6 VRNA (in), 7 VCMOA (in), 9 VCMOB (in), 10 VRNB (in), 11 VRPB (in), 13 VINB+ (in), 14 VINB- (in), 18 CLK (in), 19 OF/DCS (in), 20 PD_B (in), 21 DB0 (LSB) (out), 22 DB1 (out), 23 DB2 (out), 24 DB3 (out), 27 DB4 (out), 28 DB5 (out), 29 DB6 (out), 30 DB7 (out), 31 DB8 (out), 32 DB9 (out), 33 DB10 (out), 34 DB11 (out), 35 DB12 (out), 36 DB13 (MSB) (out), 39 DRDY (in), 40 DA0 (LSB) (out), 41 DA1 (out), 42 DA2 (out), 43 DA3 (out), 44 DA4 (out), 45 DA5 (out), 46 DA6 (out), 47 DA7 (out), 48 DA8 (out), 49 DA9 (out), 52 DA10 (out), 53 DA11 (out), 54 DA12 (out), 55 DA13 (MSB) (out), 56 NC, 57 PD_A (in), 59 VREF (in)
part B pins: 1 AGND (power), 4 AGND (power), 8 VA (power), 12 AGND (power), 15 AGND (power), 16 VA (power), 17 VA (power), 25 DRGND (power), 26 VDR (power), 37 DRGND (power), 38 VDR (power), 50 VDR (power), 51 DRGND (power), 58 VA (power), 60 VA (power), 61 AGND (power)

## ADC14DS080CISQ
designator U?
Dual 14-Bit, 80 MSPS A/D Converter with Serial LVDS Outputs; PartNumber: ADC14DS080CISQ; Manufacturer: National Semiconductor; CompType: ADC IC; PackageTopMarking: NS*UZXYTT*14DS080; PowerWise: Y
footprint SQA60A (QFN, 60-Leads, Body 9x9mm, Pitch 0.5mm, NSC Recommended)
pins: 1 AGND (power), 2 VINA- (in), 3 VINA+ (in), 4 AGND (power), 5 VRPA, 6 VRNA, 7 VCMOA, 8 VA (power), 9 VCMOB, 10 VRNB, 11 VRPB, 12 AGND (power), 13 VINB+ (in), 14 VINB- (in), 15 AGND (power), 16 VA (power), 17 VA (power), 18 CLK (in), 19 OF/DCS (in), 20 PD_B (in), 21 NC, 22 NC, 23 NC, 24 DLL_LOCK, 25 DRGND (power), 26 VDR, 27 TEST (in), 28 RESET_DLL (out), 29 LVDS_BIAS, 30 ORB (out), 31 SD0_B- (out), 32 SD0_B+ (out), 33 SD1_B- (out), 34 SD1_B+ (out), 35 SD0_A- (out), 36 SD0_A+ (out), 37 SD1_A- (out), 38 SD1_A+ (out), 39 DRGND (power), 40 VDR, 41 NC, 42 FRAME- (out), 43 FRAME+ (out), 44 OUTCLK- (out), 45 OUTCLK+ (out), 46 ORA (out), 47 WAM (in), 48 DLC (in), 49 NC, 50 VDR, 51 DRGND (power), 52 SCLK (in), 53 SDO (hiz), 54 SDI (in), 55 SCSB, 56 SPI_EN (in), 57 PD_A (in), 58 VA (power), 59 VREF, 60 VA (power), 61 DAP

## ADC14DS105AISQ
designator U?
Dual 14-Bit, 105 MSPS A/D Converter with Serial LVDS Outputs; PartNumber: ADC14DS105AISQ; Manufacturer: National Semiconductor; CompType: ADC IC; PackageTopMarking: NS*UZXYTT*14DS105A; PowerWise: N
footprint SQA60A (QFN, 60-Leads, Body 9x9mm, Pitch 0.5mm, NSC Recommended)
pins: 1 AGND (power), 2 VINA- (in), 3 VINA+ (in), 4 AGND (power), 5 VRPA, 6 VRNA, 7 VCMOA, 8 VA (power), 9 VCMOB, 10 VRNB, 11 VRPB, 12 AGND (power), 13 VINB+ (in), 14 VINB- (in), 15 AGND (power), 16 VA (power), 17 VA (power), 18 CLK (in), 19 OF/DCS (in), 20 PD_B (in), 21 NC, 22 NC, 23 NC, 24 DLL_LOCK (out), 25 DRGND (power), 26 VDR (power), 27 TEST (in), 28 RESET_DLL (in), 29 LVDS_BIAS, 30 ORB (out), 31 SD0_B- (out), 32 SD0_B+ (out), 33 SD1_B- (out), 34 SD1_B+ (out), 35 SD0_A- (out), 36 SD0_A+ (out), 37 SD1_A- (out), 38 SD1_A+ (out), 39 DRGND (power), 40 VDR (power), 41 NC, 42 FRAME- (out), 43 FRAME+ (out), 44 OUTCLK- (out), 45 OUTCLK+ (out), 46 ORA (out), 47 WAM (in), 48 DLC (in), 49 NC, 50 VDR (power), 51 DRGND (power), 52 SCLK (in), 53 SDO (out), 54 SDI (in), 55 SCSB (in), 56 SPI_EN (in), 57 PD_A (in), 58 VA (power), 59 VREF (power), 60 VA (power), 61 AGND (power)

## ADC14DS105CISQ
designator U?
Dual 14-Bit, 105 MSPS A/D Converter with Serial LVDS Outputs; PartNumber: ADC14DS105CISQ; Manufacturer: National Semiconductor; CompType: ADC IC; PackageTopMarking: NS*UZXYTT*14DS105C; PowerWise: Y
footprint SQA60A (QFN, 60-Leads, Body 9x9mm, Pitch 0.5mm, NSC Recommended)
pins: 1 AGND (power), 2 VINA- (in), 3 VINA+ (in), 4 AGND (power), 5 VRPA, 6 VRNA, 7 VCMOA, 8 VA (power), 9 VCMOB, 10 VRNB, 11 VRPB, 12 AGND (power), 13 VINB+ (in), 14 VINB- (in), 15 AGND (power), 16 VA (power), 17 VA (power), 18 CLK (in), 19 OF/DCS (in), 20 PD_B (in), 21 NC, 22 NC, 23 NC, 24 DLL_LOCK (out), 25 DRGND (power), 26 VDR (power), 27 TEST (in), 28 RESET_DLL (in), 29 LVDS_BIAS, 30 ORB (out), 31 SD0_B- (out), 32 SD0_B+ (out), 33 SD1_B- (out), 34 SD1_B+ (out), 35 SD0_A- (out), 36 SD0_A+ (out), 37 SD1_A- (out), 38 SD1_A+ (out), 39 DRGND (power), 40 VDR (power), 41 NC, 42 FRAME- (out), 43 FRAME+ (out), 44 OUTCLK- (out), 45 OUTCLK+ (out), 46 ORA (out), 47 WAM (in), 48 DLC (in), 49 NC, 50 VDR (power), 51 DRGND (power), 52 SCLK (in), 53 SDO (out), 54 SDI (in), 55 SCSB (in), 56 SPI_EN (in), 57 PD_A (in), 58 VA (power), 59 VREF (power), 60 VA (power), 61 AGND (power)

## ADC14L020CIVY
designator U?
14-Bit, 20 MSPS, 150 mW A/D Converter; PartNumber: ADC14L020CIVY; Manufacturer: National Semiconductor; CompType: ADC IC; PackageTopMarking: NSUZXYTT*ADC14L0*20CIVY; PowerWise: Y
footprint VBE32A_N (Thin QFP, 32-Leads, Body 7x7mm, Pitch 0.8mm, IPC Medium Density)
footprint VBE32A_L (Thin QFP, 32-Leads, Body 7x7mm, Pitch 0.8mm, IPC High Density)
footprint VBE32A_M (Thin QFP, 32-Leads, Body 7x7mm, Pitch 0.8mm, IPC Low Density)
pins: 1 VREF (power), 2 VIN+ (in), 3 VIN- (in), 4 AGND (power), 5 VA (power), 6 VD (power), 7 AGND (power), 8 PD (in), 9 DGND (power), 10 CLK (in), 11 DF/DCS (in), 12 D0 (out), 13 D1 (out), 14 D2 (out), 15 D3 (out), 16 D4 (out), 17 D5 (out), 18 D6 (out), 19 D7 (out), 20 DRGND (power), 21 VDR (power), 22 D8 (out), 23 D9 (out), 24 D10 (out), 25 D11 (out), 26 D12 (out), 27 D13 (out), 28 AGND (power), 29 VA (power), 30 VRN, 31 VRP, 32 VRM

## ADC14L040CIVY
designator U?
14-Bit, 40 MSPS, 235 mW A/D Converter; PartNumber: ADC14L040CIVY; Manufacturer: National Semiconductor; CompType: ADC IC; PackageTopMarking: NSUZXYTT*ADC14L0*40CIVY; PowerWise: Y
footprint VBE32A_N (Thin QFP, 32-Leads, Body 7x7mm, Pitch 0.8mm, IPC Medium Density)
footprint VBE32A_L (Thin QFP, 32-Leads, Body 7x7mm, Pitch 0.8mm, IPC High Density)
footprint VBE32A_M (Thin QFP, 32-Leads, Body 7x7mm, Pitch 0.8mm, IPC Low Density)
pins: 1 VREF (power), 2 VIN+ (in), 3 VIN- (in), 4 AGND (power), 5 VA (power), 6 VD (power), 7 AGND (power), 8 PD (in), 9 DGND (power), 10 CLK (in), 11 DF/DCS (in), 12 D0 (out), 13 D1 (out), 14 D2 (out), 15 D3 (out), 16 D4 (out), 17 D5 (out), 18 D6 (out), 19 D7 (out), 20 DRGND (power), 21 VDR (power), 22 D8 (out), 23 D9 (out), 24 D10 (out), 25 D11 (out), 26 D12 (out), 27 D13 (out), 28 AGND (power), 29 VA (power), 30 VRN, 31 VRP, 32 VRM

## ADC14V155CISQ
designator U?
14-Bit, 155 MSPS, 1.1 GHz Bandwidth A/D Converter with LVDS Outputs; PartNumber: ADC14V155CISQ; Manufacturer: National Semiconductor; CompType: ADC IC; PackageTopMarking: NS*UZXYTT*14V155SQ; PowerWise: Y
footprint SQA48A (QFN, 48-Leads, Body 7x7mm, Pitch 0.5mm, NSC Recommended)
pins: 1 VA (power), 2 AGND (power), 3 VIN- (in), 4 VIN+ (in), 5 AGND (power), 6 VA (power), 7 PD/SLEEP (in), 8 CLK_SEL/DF (in), 9 VA (power), 10 AGND (power), 11 CLK+ (in), 12 CLK- (in), 13 VD (power), 14 DGND (power), 15 OVR- (out), 16 OVR+ (out), 17 D1-/D0- (out), 18 D1+/D0+ (out), 19 D3-/D2- (out), 20 D3+/D2+ (out), 21 D5-/D4- (out), 22 D5+/D4+ (out), 23 D7-/D6- (out), 24 D7+/D6+ (out), 25 VDR (power), 26 DRGND (power), 27 D9-/D8- (out), 28 D9+/D8+ (out), 29 D11-/D10- (out), 30 D11+/D10+ (out), 31 D13-/D12- (out), 32 D13+/D12+ (out), 33 DRDY- (out), 34 DRDY+ (out), 35 DRGND (power), 36 VDR (power), 37 VA (power), 38 AGND (power), 39 AGND (power), 40 VA (power), 41 VA (power), 42 AGND (power), 43 VRP, 44 VRN, 45 VRM, 46 VREF (power), 47 AGND (power), 48 VA (power), 49 DAP (power)

## ADC16V130CISQ
designator U?
16-Bit, 130 MSPS A/D Converter with LVDS Outputs; PartNumber: ADC16V130CISQ; Manufacturer: National Semiconductor; CompType: ADC IC; PackageTopMarking: NS*UZXYTT*ADC16V130; PowerWise: Y
footprint SQA64A (QFN, 64-Leads, Body 9x9mm, Pitch 0.5mm, NSC Recommended)
pins: 1 CLK_SEL/DF (in), 2 VA3.0 (power), 3 AGND (power), 4 VRN, 5 VRN, 6 VRP, 7 VRP, 8 AGND (power), 9 VA1.8 (power), 10 CLK+ (in), 11 CLK- (in), 12 AGND (power), 13 VAD1.8 (power), 14 PD (in), 15 D0- (out), 16 D0+ (out), 17 D1- (out), 18 D1+ (out), 19 D2- (out), 20 D2+ (out), 21 D3- (out), 22 D3+ (out), 23 DRGND (power), 24 VDR (power), 25 D4- (out), 26 D4+ (out), 27 D5- (out), 28 D5+ (out), 29 D6- (out), 30 D6+ (out), 31 D7- (out), 32 D7+ (out), 33 OUTCLK- (out), 34 OUTCLK+ (out), 35 D8- (out), 36 D8+ (out), 37 D9- (out), 38 D9+ (out), 39 D10- (out), 40 D10+ (out), 41 D11- (out), 42 D11+ (out), 43 DRGND (power), 44 VDR (power), 45 D12- (out), 46 D12+ (out), 47 D13- (out), 48 D13+ (out), 49 D14- (out), 50 D14+ (out), 51 D15- (out), 52 D15+ (out), 53 OR- (out), 54 OR+ (out), 55 VA3.0 (power), 56 AGND (power), 57 VREF (power), 58 VRM, 59 VA3.0 (power), 60 AGND (power), 61 VIN+ (in), 62 VIN- (in), 63 AGND (power), 64 VA1.8 (power), 65 AGND (power)

## ADC78H89CIMT
designator U?
7-Channel, 500 KSPS, 12-Bit A/D Converter; PartNumber: ADC78H89CIMT; Manufacturer: National Semiconductor; CompType: ADC IC; PackageTopMarking: NSUZXYTT*78H89*CIMT; PowerWise: Y
footprint MTC16_N (TSOP, 16-Leads, Body 5x4.4mm, Pitch 0.65mm, IPC Medium Density)
footprint MTC16_L (TSOP, 16-Leads, Body 5x4.4mm, Pitch 0.65mm, IPC High Density)
footprint MTC16_M (TSOP, 16-Leads, Body 5x4.4mm, Pitch 0.65mm, IPC Low Density)
pins: 1 ~{CS} (in), 2 NC, 3 AVDD (power), 4 GND (power), 5 AIN1 (in), 6 AIN2 (in), 7 AIN3 (in), 8 AIN4 (in), 9 AIN5 (in), 10 AIN6 (in), 11 AIN7 (in), 12 GND (power), 13 DVDD (power), 14 DIN (in), 15 DOUT (out), 16 SCLK (in)

## ADC78H90CIMT
designator U?
8-Channel, 500 KSPS, 12-Bit A/D Converter; PartNumber: ADC78H90CIMT; Manufacturer: National Semiconductor; CompType: ADC IC; PackageTopMarking: NSUZXYTT*78H90*CIMT; PowerWise: Y
footprint MTC16_N (TSOP, 16-Leads, Body 5x4.4mm, Pitch 0.65mm, IPC Medium Density)
footprint MTC16_L (TSOP, 16-Leads, Body 5x4.4mm, Pitch 0.65mm, IPC High Density)
footprint MTC16_M (TSOP, 16-Leads, Body 5x4.4mm, Pitch 0.65mm, IPC Low Density)
pins: 1 ~{CS} (in), 2 AVDD (power), 3 AGND (power), 4 AIN1 (in), 5 AIN2 (in), 6 AIN3 (in), 7 AIN4 (in), 8 AIN5 (in), 9 AIN6 (in), 10 AIN7 (in), 11 AIN8 (in), 12 DGND (power), 13 DVDD (power), 14 DIN (in), 15 DOUT (out), 16 SCLK (in)

## ADC081C021CIMK
designator U?
I2C-Compatible, 8-Bit Analog-to-Digital Converter (ADC) with Alert Pin; PartNumber: ADC081C021CIMK; Manufacturer: National Semiconductor; CompType: ADC IC; PackageTopMarking: X34C*XTT; PowerWise: N
footprint MK06A_N (SOT23, 6-Leads, Body 3.0x1.7mm, Pitch 0.95mm, Lead Span 2.9mm, IPC Medium Density)
footprint MK06A_L (SOT23, 6-Leads, Body 3.0x1.7mm, Pitch 0.95mm, Lead Span 2.9mm, IPC High Density)
footprint MK06A_M (SOT23, 6-Leads, Body 3.0x1.7mm, Pitch 0.95mm, Lead Span 2.9mm, IPC Low Density)
pins: 1 VA (power), 2 GND (power), 3 VIN (in), 4 ALERT (oc), 5 SCL (in), 6 SDA (io)

## ADC081C021CIMM
designator U?
I2C-Compatible, 8-Bit Analog-to-Digital Converter with Alert Pin; PartNumber: ADC081C021CIMM; Manufacturer: National Semiconductor; CompType: ADC IC; PackageTopMarking: ZXTT*X36C; PowerWise: N
footprint MUA08A_N (TSOP, 8-Leads, Body 3x3mm, Pitch 0.65mm, IPC Medium Density)
footprint MUA08A_L (TSOP, 8-Leads, Body 3x3mm, Pitch 0.65mm, IPC High Density)
footprint MUA08A_M (TSOP, 8-Leads, Body 3x3mm, Pitch 0.65mm, IPC Low Density)
pins: 1 SCL (in), 2 ALERT (oc), 3 ADDR0 (in), 4 VIN (in), 5 VA (power), 6 ADDR1 (in), 7 GND (power), 8 SDA (io)

## ADC081C027CIMK
designator U?
I2C-Compatible, 8-Bit Analog-to-Digital Converter (ADC) with Alert Function; PartNumber: ADC081C027CIMK; Manufacturer: National Semiconductor; CompType: ADC IC; PackageTopMarking: X35C*XTT; PowerWise: N
footprint MK06A_N (SOT23, 6-Leads, Body 3.0x1.7mm, Pitch 0.95mm, Lead Span 2.9mm, IPC Medium Density)
footprint MK06A_L (SOT23, 6-Leads, Body 3.0x1.7mm, Pitch 0.95mm, Lead Span 2.9mm, IPC High Density)
footprint MK06A_M (SOT23, 6-Leads, Body 3.0x1.7mm, Pitch 0.95mm, Lead Span 2.9mm, IPC Low Density)
pins: 1 VA (power), 2 GND (power), 3 VIN (in), 4 ADDR (in), 5 SCL (in), 6 SDA (io)

## ADC081S021CIMF
designator U?
Single Channel, 50 to 200 ksps, 8-Bit A/D Converter; PartNumber: ADC081S021CIMF; Manufacturer: National Semiconductor; CompType: ADC IC; PackageTopMarking: X09C*XTT; PowerWise: Y
footprint MF06A_N (SOT23, 6-Leads, Body 2.9x1.6mm, Pitch 0.95mm, Lead Span 2.8mm, IPC Medium Density)
footprint MF06A_L (SOT23, 6-Leads, Body 2.9x1.6mm, Pitch 0.95mm, Lead Span 2.8mm, IPC High Density)
footprint MF06A_M (SOT23, 6-Leads, Body 2.9x1.6mm, Pitch 0.95mm, Lead Span 2.8mm, IPC Low Density)
pins: 1 VA (power), 2 GND (power), 3 VIN (in), 4 SCLK (in), 5 SDATA (out), 6 ~{CS} (in)

## ADC081S021CISD
designator U?
Single Channel, 50 to 200 ksps, 8-Bit A/D Converter; PartNumber: ADC081S021CISD; Manufacturer: National Semiconductor; CompType: ADC IC; PackageTopMarking: XTT*X9C; PowerWise: Y
footprint SDB06A (SON, 6-Leads, Body 2.2x2.5mm, Pitch 0.65mm, NSC Recommended (SC-70 Land))
pins: 1 VA (power), 2 GND (power), 3 VIN (in), 4 SCLK (in), 5 SDATA (out), 6 ~{CS} (in), 7 GND (power)

## ADC081S051CIMF
designator U?
Single Channel, 200 to 500 ksps, 8-Bit A/D Converter; PartNumber: ADC081S051CIMF; Manufacturer: National Semiconductor; CompType: ADC IC; PackageTopMarking: X15C*XTT; PowerWise: Y
footprint MF06A_N (SOT23, 6-Leads, Body 2.9x1.6mm, Pitch 0.95mm, Lead Span 2.8mm, IPC Medium Density)
footprint MF06A_L (SOT23, 6-Leads, Body 2.9x1.6mm, Pitch 0.95mm, Lead Span 2.8mm, IPC High Density)
footprint MF06A_M (SOT23, 6-Leads, Body 2.9x1.6mm, Pitch 0.95mm, Lead Span 2.8mm, IPC Low Density)
pins: 1 VA (power), 2 GND (power), 3 VIN (in), 4 SCLK (in), 5 SDATA (out), 6 ~{CS} (in)

## ADC081S051CISD
designator U?
Single Channel, 200 to 500 ksps, 8-Bit A/D Converter; PartNumber: ADC081S051CISD; Manufacturer: National Semiconductor; CompType: ADC IC; PackageTopMarking: XTT*X6C; PowerWise: Y
footprint SDB06A (SON, 6-Leads, Body 2.2x2.5mm, Pitch 0.65mm, NSC Recommended (SC-70 Land))
pins: 1 VA (power), 2 GND (power), 3 VIN (in), 4 SCLK (in), 5 SDATA (out), 6 ~{CS} (in), 7 GND (power)

## ADC081S101CIMF
designator U?
1MSPS, 8-Bit A/D Converter in SOT-23; PartNumber: ADC081S101CIMF; Manufacturer: National Semiconductor; CompType: ADC IC; PackageTopMarking: X03C*XTT; PowerWise: Y
footprint MF06A_N (SOT23, 6-Leads, Body 2.9x1.6mm, Pitch 0.95mm, Lead Span 2.8mm, IPC Medium Density)
footprint MF06A_L (SOT23, 6-Leads, Body 2.9x1.6mm, Pitch 0.95mm, Lead Span 2.8mm, IPC High Density)
footprint MF06A_M (SOT23, 6-Leads, Body 2.9x1.6mm, Pitch 0.95mm, Lead Span 2.8mm, IPC Low Density)
pins: 1 VA (power), 2 GND (power), 3 VIN (in), 4 SCLK (in), 5 SDATA (out), 6 ~{CS} (in)

## ADC081S101CISD
designator U?
1MSPS, 8-Bit A/D Converter in SOT-23; PartNumber: ADC081S101CISD; Manufacturer: National Semiconductor; CompType: ADC IC; PackageTopMarking: XTT*X3C; PowerWise: Y
footprint SDB06A (SON, 6-Leads, Body 2.2x2.5mm, Pitch 0.65mm, NSC Recommended (SC-70 Land))
pins: 1 VA (power), 2 GND (power), 3 VIN (in), 4 SCLK (in), 5 SDATA (out), 6 ~{CS} (in), 7 GND (power)

## ADC082S021CIMM
designator U?
2 Channel, 200 KSPS, 8-Bit A/D Converter; PartNumber: ADC082S021CIMM; Manufacturer: National Semiconductor; CompType: ADC IC; PackageTopMarking: ZXTT*X16C; PowerWise: Y
footprint MUA08A_N (TSOP, 8-Leads, Body 3x3mm, Pitch 0.65mm, IPC Medium Density)
footprint MUA08A_L (TSOP, 8-Leads, Body 3x3mm, Pitch 0.65mm, IPC High Density)
footprint MUA08A_M (TSOP, 8-Leads, Body 3x3mm, Pitch 0.65mm, IPC Low Density)
pins: 1 ~{CS} (in), 2 VA (power), 3 GND (power), 4 IN2 (in), 5 IN1 (in), 6 DIN (in), 7 DOUT (out), 8 SCLK (in)

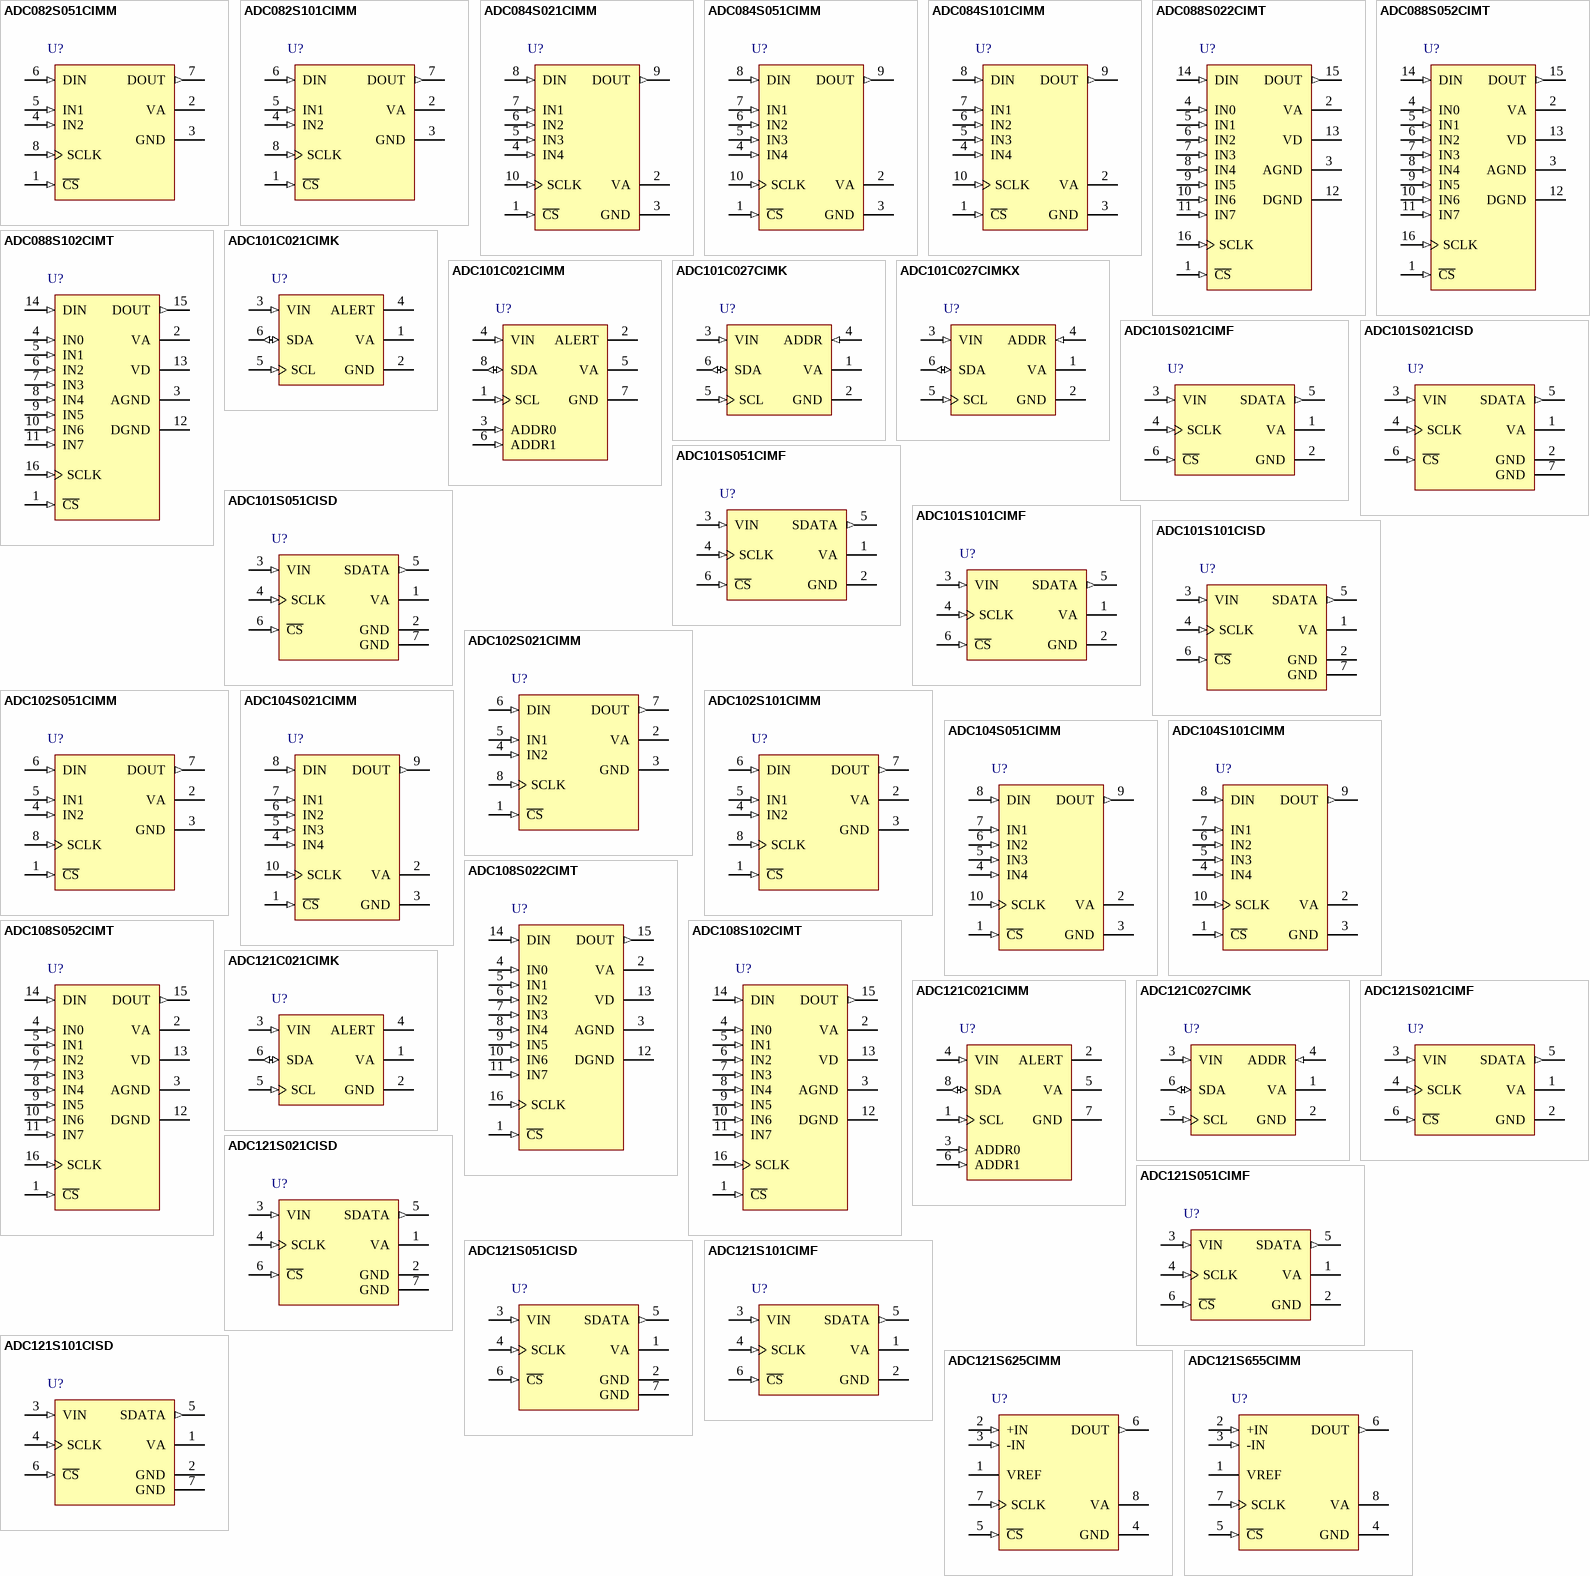
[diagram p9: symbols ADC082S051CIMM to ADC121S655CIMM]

## ADC082S051CIMM
designator U?
2 Channel, 500 kSPS, 8-Bit A/D Converter; PartNumber: ADC082S051CIMM; Manufacturer: National Semiconductor; CompType: ADC IC; PackageTopMarking: ZXTT*X04C; PowerWise: Y
footprint MUA08A_N (TSOP, 8-Leads, Body 3x3mm, Pitch 0.65mm, IPC Medium Density)
footprint MUA08A_L (TSOP, 8-Leads, Body 3x3mm, Pitch 0.65mm, IPC High Density)
footprint MUA08A_M (TSOP, 8-Leads, Body 3x3mm, Pitch 0.65mm, IPC Low Density)
pins: 1 ~{CS} (in), 2 VA (power), 3 GND (power), 4 IN2 (in), 5 IN1 (in), 6 DIN (in), 7 DOUT (out), 8 SCLK (in)

## ADC082S101CIMM
designator U?
2 Channel, 1 MSPS, 8-Bit A/D Converter; PartNumber: ADC082S101CIMM; Manufacturer: National Semiconductor; CompType: ADC IC; PackageTopMarking: ZXTT*X22C; PowerWise: Y
footprint MUA08A_N (TSOP, 8-Leads, Body 3x3mm, Pitch 0.65mm, IPC Medium Density)
footprint MUA08A_L (TSOP, 8-Leads, Body 3x3mm, Pitch 0.65mm, IPC High Density)
footprint MUA08A_M (TSOP, 8-Leads, Body 3x3mm, Pitch 0.65mm, IPC Low Density)
pins: 1 ~{CS} (in), 2 VA (power), 3 GND (power), 4 IN2 (in), 5 IN1 (in), 6 DIN (in), 7 DOUT (out), 8 SCLK (in)

## ADC084S021CIMM
designator U?
4 Channel, 200 KSPS, 8-Bit A/D Converter; PartNumber: ADC084S021CIMM; Manufacturer: National Semiconductor; CompType: ADC IC; PackageTopMarking: ZXTT*X19C; PowerWise: Y
footprint MUB10A_N (TSSOP, 10-Leads, Body 3x3mm, Pitch 0.5mm, IPC Medium Density)
footprint MUB10A_L (TSSOP, 10-Leads, Body 3x3mm, Pitch 0.5mm, IPC High Density)
footprint MUB10A_M (TSSOP, 10-Leads, Body 3x3mm, Pitch 0.5mm, IPC Low Density)
pins: 1 ~{CS} (in), 2 VA (power), 3 GND (power), 4 IN4 (in), 5 IN3 (in), 6 IN2 (in), 7 IN1 (in), 8 DIN (in), 9 DOUT (out), 10 SCLK (in)

## ADC084S051CIMM
designator U?
4 Channel, 500 kSPS, 8-Bit A/D Converter; PartNumber: ADC084S051CIMM; Manufacturer: National Semiconductor; CompType: ADC IC; PackageTopMarking: ZXTT*X10C; PowerWise: Y
footprint MUB10A_N (TSSOP, 10-Leads, Body 3x3mm, Pitch 0.5mm, IPC Medium Density)
footprint MUB10A_L (TSSOP, 10-Leads, Body 3x3mm, Pitch 0.5mm, IPC High Density)
footprint MUB10A_M (TSSOP, 10-Leads, Body 3x3mm, Pitch 0.5mm, IPC Low Density)
pins: 1 ~{CS} (in), 2 VA (power), 3 GND (power), 4 IN4 (in), 5 IN3 (in), 6 IN2 (in), 7 IN1 (in), 8 DIN (in), 9 DOUT (out), 10 SCLK (in)

## ADC084S101CIMM
designator U?
4 Channel, 1 MSPS, 8-Bit A/D Converter; PartNumber: ADC084S101CIMM; Manufacturer: National Semiconductor; CompType: ADC IC; PackageTopMarking: ZXTT*X25C; PowerWise: Y
footprint MUB10A_N (TSSOP, 10-Leads, Body 3x3mm, Pitch 0.5mm, IPC Medium Density)
footprint MUB10A_L (TSSOP, 10-Leads, Body 3x3mm, Pitch 0.5mm, IPC High Density)
footprint MUB10A_M (TSSOP, 10-Leads, Body 3x3mm, Pitch 0.5mm, IPC Low Density)
pins: 1 ~{CS} (in), 2 VA (power), 3 GND (power), 4 IN4 (in), 5 IN3 (in), 6 IN2 (in), 7 IN1 (in), 8 DIN (in), 9 DOUT (out), 10 SCLK (in)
